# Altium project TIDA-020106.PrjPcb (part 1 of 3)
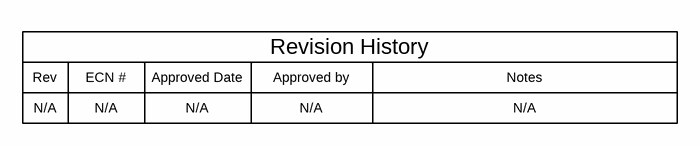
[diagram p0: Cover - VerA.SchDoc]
CopyrightYear: 2025; EVM_orderable: No; Orderable: NO; PCB_Layout: Hely Zhang; PCB_Rev: VerA; PRJ_Customer: Public Release; PRJ_Engineer: Hely Zhang; PRJ_Number: TIDA-020106; PRJ_Title: TIDA-020106; SCH_Rev: VerB; TechSupport: http://www.ti.com/support; TID: TIDA-020106
15 sheets, 408 parts. Net scope: hierarchical (ports join the sheet entries above them; power ports are global).
Board file: TIDA-020106.PcbDoc
Sheets:
  Cover - VerA.SchDoc
  Main.SchDoc
    U_DC_DC = DC_DC.SchDoc
    U_Hardware = Hardware.SchDoc
    DSP = DSP.SchDoc
      U_Clock_Reset = Clock_Reset.SchDoc
      U_ADC = ADC.SchDoc
      U_GPIO_Power = GPIO_Power.SchDoc
    CAN = CAN.SchDoc
    Sensor = Sensor.SchDoc
    PMIC = PMIC.SchDoc
    EPB = EPB.SchDoc
    BLDC = BLDC.SchDoc
    Ideal Diode = ID1_LM74930.SchDoc
  Cover - VerB.SchDoc

## Sheet Cover - VerA.SchDoc: Cover
size 431 x 279 mm; Date: Not shown in title block; ApprovedBy: Not shown in title block; CheckedBy: Not shown in title block; Author: Not shown in title block; CompanyName: Not shown in title block; Engineer: Not shown in title block; Organization: Not shown in title block; Address1: Not shown in title block; Address2: Not shown in title block; Address3: Not shown in title block; Address4: Not shown in title block; DocumentNumber: 1; Revision: Use project parameter SCH_Rev; SheetNumber: 1; SheetTotal: 15; PageSetup: Record=PageOptions¦CenterHorizontal=True¦CenterVertical=True¦PrintScale=1.00¦XCorrection=1.00¦YCorrection=1.00¦PrintKind=0¦BorderSize=5000000¦LeftOffset=0¦BottomOffset=0¦Orientation=2¦PaperLength=1000¦PaperWidth=1000¦Scale=100¦PaperSource=15¦PrintQuality=600¦MediaType=1¦DitherType=10¦PaperKind=Letter¦PrintScaleMode=1

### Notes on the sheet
- Rev
- N/A
- ECN #
- Approved Date
- Approved by
- Revision History
- Notes

## Sheet Main.SchDoc: Main
size 431 x 279 mm; Date: Not shown in title block; ApprovedBy: Not shown in title block; CheckedBy: Not shown in title block; Author: Not shown in title block; CompanyName: Not shown in title block; DrawnBy: Hely Zhang; Engineer: Not shown in title block; Organization: Not shown in title block; Address1: Not shown in title block; Address2: Not shown in title block; Address3: Not shown in title block; Address4: Not shown in title block; DocumentNumber: 2; Revision: Use project parameter SCH_Rev; SheetNumber: 2; SheetTotal: 15; PageSetup: Record=PageOptions¦CenterHorizontal=True¦CenterVertical=True¦PrintScale=1.00¦XCorrection=1.00¦YCorrection=1.00¦PrintKind=0¦BorderSize=5000000¦LeftOffset=0¦BottomOffset=0¦Orientation=2¦PaperLength=1000¦PaperWidth=1000¦Scale=100¦PaperSource=15¦PrintQuality=600¦MediaType=1¦DitherType=10¦PaperKind=Letter¦PrintScaleMode=1
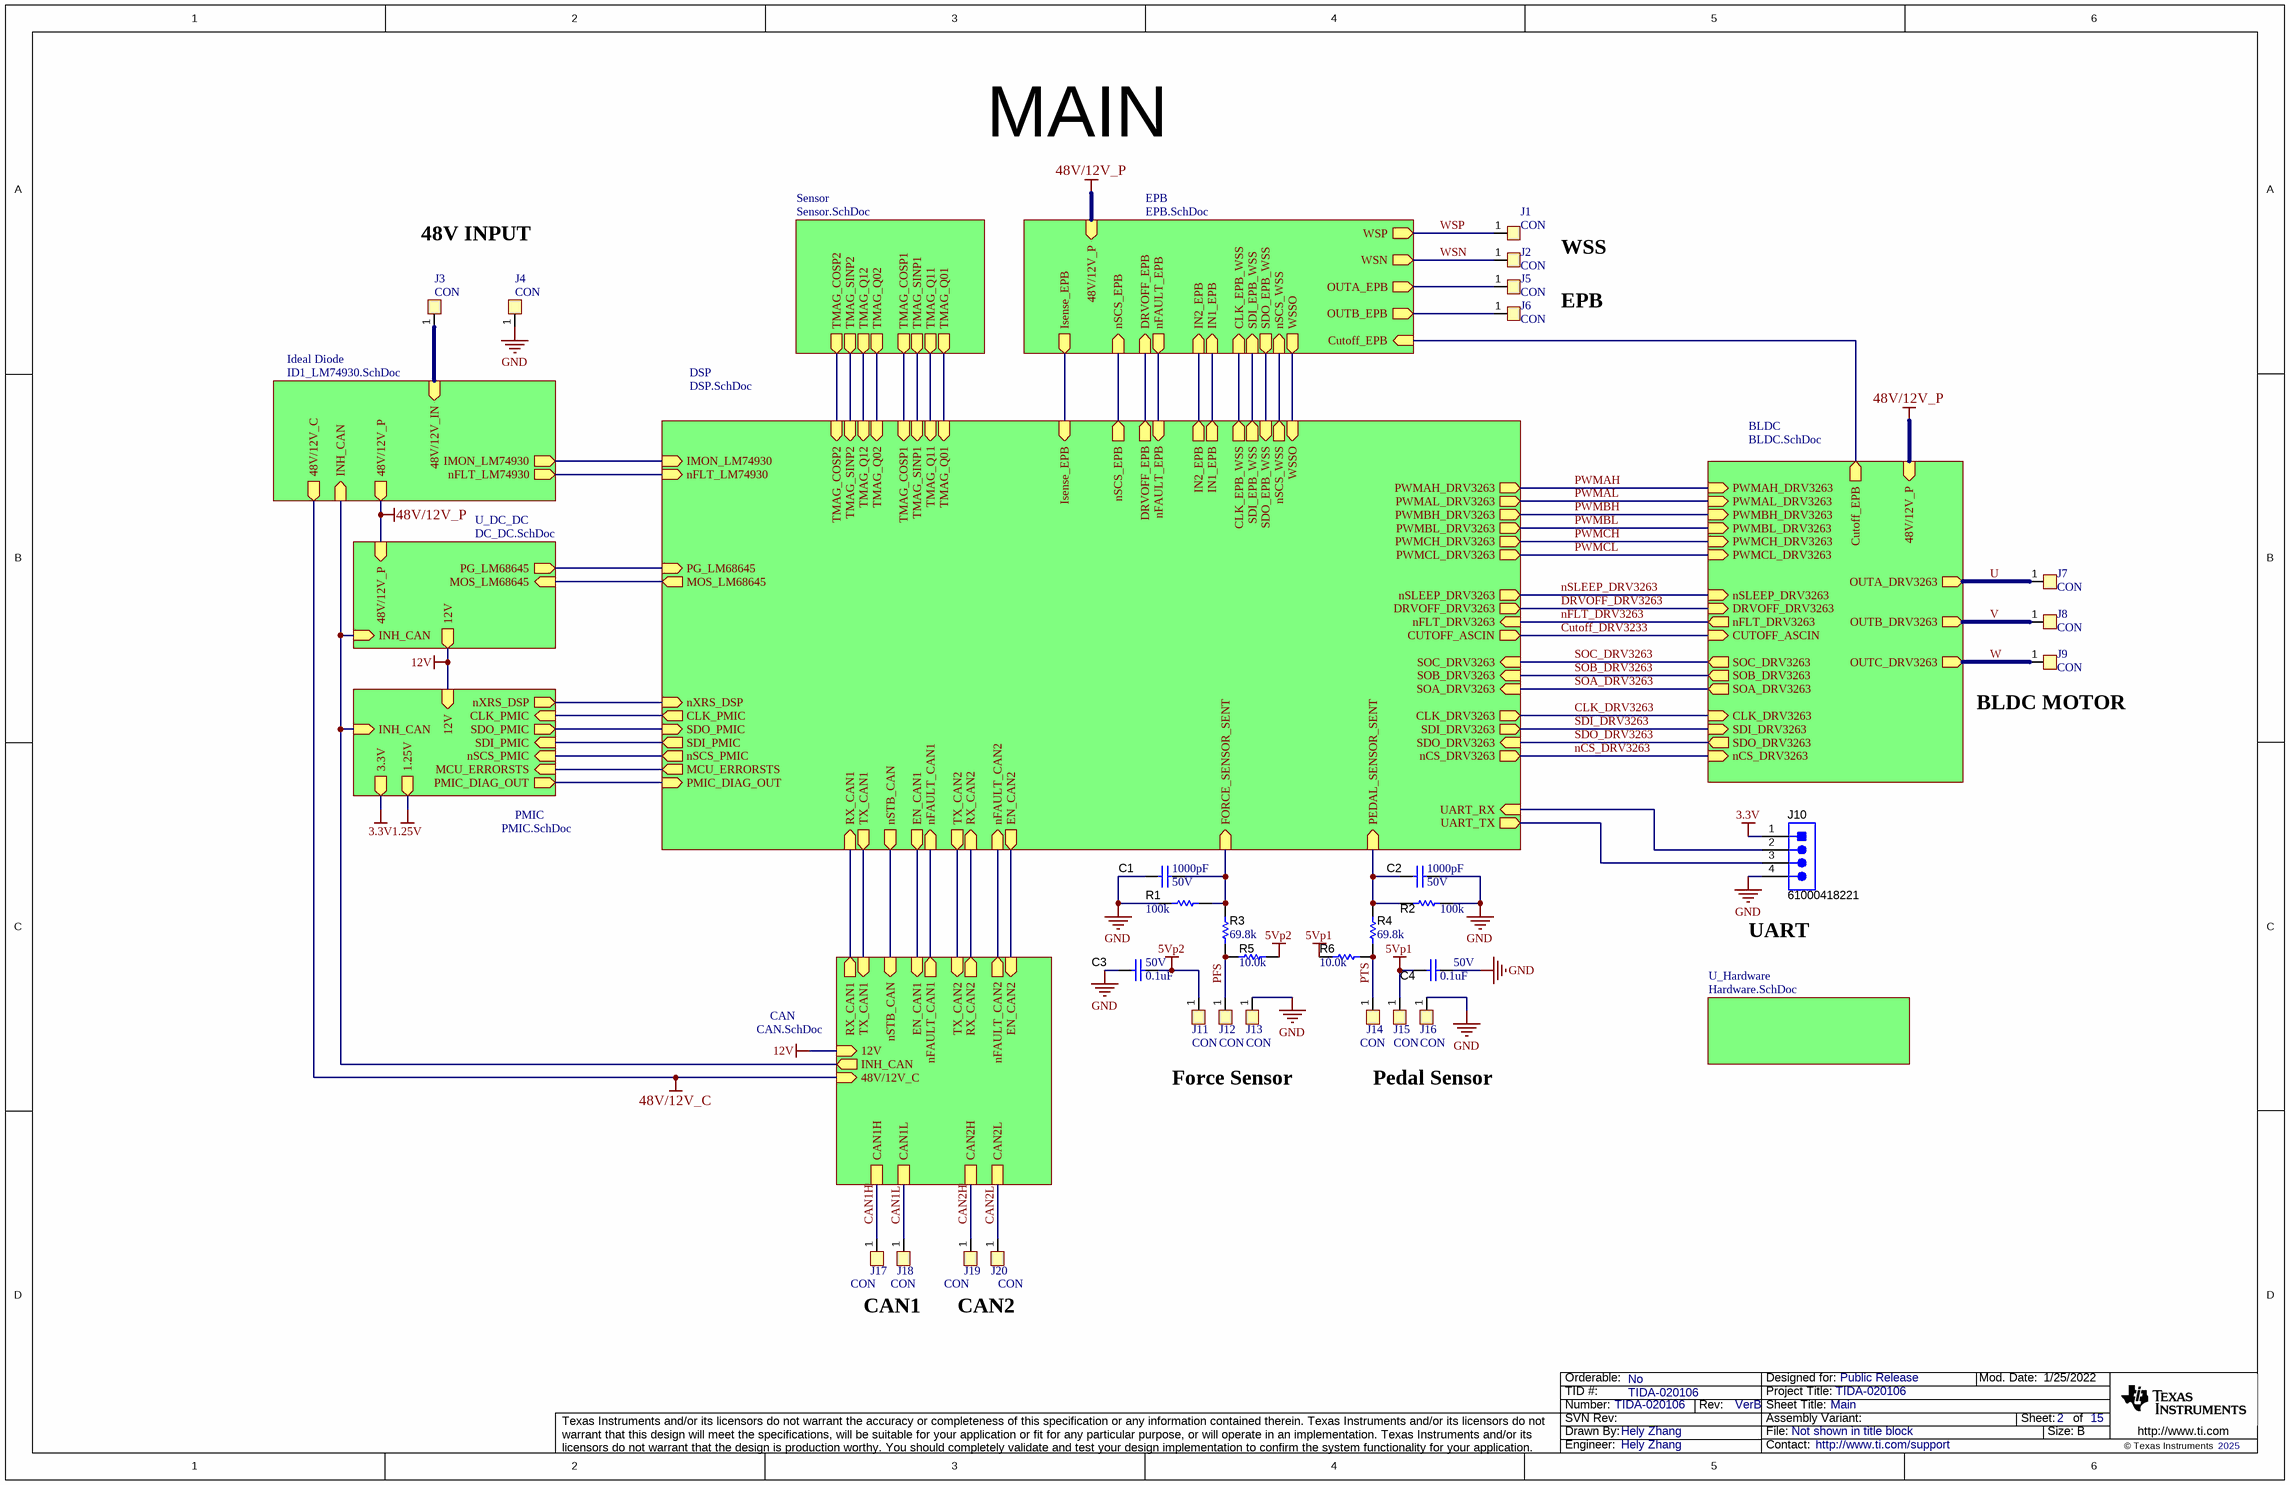
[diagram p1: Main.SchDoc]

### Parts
C1  ValueDisplayed: 1000pF  VDC_V: 50V  [0402]  (hidden comment: CGA2B2X8R1H102K050BA)
C2  ValueDisplayed: 1000pF  VDC_V: 50V  [0402]  (hidden comment: CGA2B2X8R1H102K050BA)
C3  VDC_V: 50V  ValueDisplayed: 0.1uF  [0402]  (hidden comment: GCM155R71H104KE02D)
C4  VDC_V: 50V  ValueDisplayed: 0.1uF  [0402]  (hidden comment: GCM155R71H104KE02D)
J1  CON  [Pin_1.7x1.1mm]
J2  CON  [Pin_1.7x1.1mm]
J3  CON  [Pin_3.3x1.3mm]
J4  CON  [Pin_3.3x1.3mm]
J5  CON  [Pin_1.9x0.9mm]
J6  CON  [Pin_1.9x0.9mm]
J7  CON  [Pin_3.3x1.4mm]
J8  CON  [Pin_3.3x1.4mm]
J9  CON  [Pin_3.3x1.4mm]
J10  61000418221  [Wurth_61000418221]
J11  CON  [Pin_1.7x1.1mm]
J12  CON  [Pin_1.7x1.1mm]
J13  CON  [Pin_1.7x1.1mm]
J14  CON  [Pin_1.7x1.1mm]
J15  CON  [Pin_3.3x1.3mm]
J16  CON  [Pin_1.7x1.1mm]
J17  CON  [Pin_1.7x1.1mm]
J18  CON  [Pin_1.7x1.1mm]
J19  CON  [Pin_1.7x1.1mm]
J20  CON  [Pin_1.7x1.1mm]
R1  ValueDisplayed: 100k  [0402]  (hidden comment: CRCW0402100KFKED)
R2  ValueDisplayed: 100k  [0402]  (hidden comment: CRCW0402100KFKED)
R3  ValueDisplayed: 69.8k  [0402]  (hidden comment: CRCW040269K8FKED)
R4  ValueDisplayed: 69.8k  [0402]  (hidden comment: CRCW040269K8FKED)
R5  ValueDisplayed: 10.0k  [0402]  (hidden comment: CRCW040210K0FKED)
R6  ValueDisplayed: 10.0k  [0402]  (hidden comment: CRCW040210K0FKED)

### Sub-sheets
BLDC = BLDC.SchDoc: nFLT_DRV3263 (out), PWMAH_DRV3263 (in), PWMAL_DRV3263 (in), PWMBH_DRV3263 (in), PWMBL_DRV3263 (in), PWMCH_DRV3263 (in), PWMCL_DRV3263 (in), SOC_DRV3263 (out), SOB_DRV3263 (out), SOA_DRV3263 (out), OUTA_DRV3263 (out), OUTB_DRV3263 (out), OUTC_DRV3263 (out), nCS_DRV3263 (in), CLK_DRV3263 (in), nSLEEP_DRV3263 (in), DRVOFF_DRV3263 (in), SDO_DRV3263 (out), SDI_DRV3263 (in), Cutoff_EPB (out), 48V/12V_P (in), CUTOFF_ASCIN (in)
CAN = CAN.SchDoc: TX_CAN1 (in), RX_CAN1 (out), nFAULT_CAN1 (out), EN_CAN1 (in), TX_CAN2 (in), RX_CAN2 (out), nFAULT_CAN2 (out), EN_CAN2 (in), 12V (in), 48V/12V_C (in), INH_CAN (out), CAN1H, CAN1L, CAN2L, CAN2H, nSTB_CAN (in)
DSP = DSP.SchDoc: CLK_PMIC (out), nSCS_PMIC (out), SOC_DRV3263 (in), SOB_DRV3263 (in), SOA_DRV3263 (in), PWMAH_DRV3263 (out), PWMAL_DRV3263 (out), PWMBH_DRV3263 (out), PWMBL_DRV3263 (out), PWMCH_DRV3263 (out), PWMCL_DRV3263 (out), nFLT_DRV3263 (in), TMAG_COSP2 (in), TMAG_SINP2 (in), TMAG_SINP1 (in), TMAG_COSP1 (in), FORCE_SENSOR_SENT (in), PEDAL_SENSOR_SENT (in), CLK_EPB_WSS (out), nFAULT_EPB (in), nSCS_WSS (out), nSCS_EPB (out), Isense_EPB (in), UART_TX (out), UART_RX (in), MCU_ERRORSTS (out), SDO_PMIC (in), SDI_PMIC (out), nXRS_DSP (in), PG_LM68645 (in), TX_CAN1 (out), RX_CAN1 (in), nFAULT_CAN1 (in), EN_CAN1 (out), TX_CAN2 (out), RX_CAN2 (in), nFAULT_CAN2 (in), EN_CAN2 (out), nSLEEP_DRV3263 (out), DRVOFF_DRV3263 (out), nCS_DRV3263 (out), CLK_DRV3263 (out), IN2_EPB (out), IN1_EPB (out), WSSO (in), SDI_DRV3263 (out), SDI_EPB_WSS (out), SDO_DRV3263 (in), SDO_EPB_WSS (in), nFLT_LM74930 (in), PMIC_DIAG_OUT (in), CUTOFF_ASCIN (out), TMAG_Q01 (in), TMAG_Q02 (in), TMAG_Q12 (in), TMAG_Q11 (in), IMON_LM74930 (in), DRVOFF_EPB (out), MOS_LM68645 (out), nSTB_CAN (out)
EPB = EPB.SchDoc: IN1_EPB (in), nFAULT_EPB (out), IN2_EPB (in), OUTA_EPB (out), OUTB_EPB (out), SDI_EPB_WSS (in), SDO_EPB_WSS (out), nSCS_EPB (in), Isense_EPB (out), WSSO (out), nSCS_WSS (in), CLK_EPB_WSS (in), 48V/12V_P (in), Cutoff_EPB (in), WSP (out), WSN (out), DRVOFF_EPB (in)
Ideal Diode = ID1_LM74930.SchDoc: nFLT_LM74930 (out), 48V/12V_P (out), 48V/12V_C (out), 48V/12V_IN (in), INH_CAN (in), IMON_LM74930 (out)
PMIC = PMIC.SchDoc: nSCS_PMIC (in), 12V (in), 3.3V (out), 1.25V (out), CLK_PMIC (in), SDO_PMIC (out), SDI_PMIC (in), nXRS_DSP (out), MCU_ERRORSTS (in), PMIC_DIAG_OUT (out), INH_CAN (in)
Sensor = Sensor.SchDoc: TMAG_COSP1 (out), TMAG_SINP1 (out), TMAG_COSP2 (out), TMAG_SINP2 (out), TMAG_Q01 (out), TMAG_Q02 (out), TMAG_Q12 (out), TMAG_Q11 (out)
U_DC_DC = DC_DC.SchDoc: PG_LM68645 (out), 12V (out), 48V/12V_P (in), INH_CAN (in), MOS_LM68645 (in)
U_Hardware = Hardware.SchDoc: no entries

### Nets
3.3V: J10.1 ; sheet PMIC/3.3V
5Vp1: C4.1 J15.1 R6.2
5Vp2: C3.2 J11.1 R5.1
12V: sheet U_DC_DC/12V, sheet CAN/12V, sheet PMIC/12V
48V/12V_C: sheet CAN/48V/12V_C, sheet Ideal Diode/48V/12V_C
48V/12V_IN: J3.1 ; sheet Ideal Diode/48V/12V_IN
48V/12V_P: sheet U_DC_DC/48V/12V_P, sheet EPB/48V/12V_P, sheet BLDC/48V/12V_P, sheet Ideal Diode/48V/12V_P
GND: C1.1 C2.2 C3.1 C4.2 J4.1 J10.4 J13.1 J16.1 R1.2 R2.1
BOOT1: J10.3 ; sheet DSP/UART_TX
CAN1H: J17.1 ; sheet CAN/CAN1H
CAN1L: J18.1 ; sheet CAN/CAN1L
CAN2H: J19.1 ; sheet CAN/CAN2H
CAN2L: J20.1 ; sheet CAN/CAN2L
CLK_DRV3263: sheet DSP/CLK_DRV3263, sheet BLDC/CLK_DRV3263
CLK_PMIC: sheet DSP/CLK_PMIC, sheet PMIC/CLK_PMIC
CLKEPB: sheet DSP/CLK_EPB_WSS, sheet EPB/CLK_EPB_WSS
Cutoff_DRV3233: sheet DSP/CUTOFF_ASCIN, sheet BLDC/CUTOFF_ASCIN  [project net CUTOFF_ASCIN]
Cutoff_EPB: sheet EPB/Cutoff_EPB, sheet BLDC/Cutoff_EPB
DRVOFF_DRV3263: sheet DSP/DRVOFF_DRV3263, sheet BLDC/DRVOFF_DRV3263
DRVOFF_EPB: sheet DSP/DRVOFF_EPB, sheet EPB/DRVOFF_EPB
EN_CAN1: sheet DSP/EN_CAN1, sheet CAN/EN_CAN1
EN_CAN2: sheet DSP/EN_CAN2, sheet CAN/EN_CAN2
FORCE_SENSOR_SENT: C1.2 R1.1 R3.2 ; sheet DSP/FORCE_SENSOR_SENT
IMON_LM74930: sheet DSP/IMON_LM74930, sheet Ideal Diode/IMON_LM74930
IN1_EPB: sheet DSP/IN1_EPB, sheet EPB/IN1_EPB
IN2_EPB: sheet DSP/IN2_EPB, sheet EPB/IN2_EPB
INH_CAN: sheet U_DC_DC/INH_CAN, sheet CAN/INH_CAN, sheet PMIC/INH_CAN, sheet Ideal Diode/INH_CAN
Isense_EPB: sheet DSP/Isense_EPB, sheet EPB/Isense_EPB
MCU_ERRORSTS: sheet DSP/MCU_ERRORSTS, sheet PMIC/MCU_ERRORSTS
MOS_LM68645: sheet U_DC_DC/MOS_LM68645, sheet DSP/MOS_LM68645
nCS_DRV3263: sheet DSP/nCS_DRV3263, sheet BLDC/nCS_DRV3263
nFAULT_CAN1: sheet DSP/nFAULT_CAN1, sheet CAN/nFAULT_CAN1
nFAULT_CAN2: sheet DSP/nFAULT_CAN2, sheet CAN/nFAULT_CAN2
nFAULT_EPB: sheet DSP/nFAULT_EPB, sheet EPB/nFAULT_EPB
nFLT_DRV3263: sheet DSP/nFLT_DRV3263, sheet BLDC/nFLT_DRV3263
nFLT_LM74930: sheet DSP/nFLT_LM74930, sheet Ideal Diode/nFLT_LM74930
nSCS_EPB: sheet DSP/nSCS_EPB, sheet EPB/nSCS_EPB
nSCS_PMIC: sheet DSP/nSCS_PMIC, sheet PMIC/nSCS_PMIC
nSCS_WSS: sheet DSP/nSCS_WSS, sheet EPB/nSCS_WSS
nSLEEP_DRV3263: sheet DSP/nSLEEP_DRV3263, sheet BLDC/nSLEEP_DRV3263
nSTB_CAN: sheet DSP/nSTB_CAN, sheet CAN/nSTB_CAN
nXRS_DSP: sheet DSP/nXRS_DSP, sheet PMIC/nXRS_DSP
OUTA_EPB: J5.1 ; sheet EPB/OUTA_EPB
OUTB_EPB: J6.1 ; sheet EPB/OUTB_EPB
PEDAL_SENSOR_SENT: C2.1 R2.2 R4.2 ; sheet DSP/PEDAL_SENSOR_SENT
PFS: J12.1 R3.1 R5.2
PG_LM68645: sheet U_DC_DC/PG_LM68645, sheet DSP/PG_LM68645
PMIC_DIAG_OUT: sheet DSP/PMIC_DIAG_OUT, sheet PMIC/PMIC_DIAG_OUT
PTS: J14.1 R4.1 R6.1
PWMAH: sheet DSP/PWMAH_DRV3263, sheet BLDC/PWMAH_DRV3263
PWMAL: sheet DSP/PWMAL_DRV3263, sheet BLDC/PWMAL_DRV3263
PWMBH: sheet DSP/PWMBH_DRV3263, sheet BLDC/PWMBH_DRV3263
PWMBL: sheet DSP/PWMBL_DRV3263, sheet BLDC/PWMBL_DRV3263
PWMCH: sheet DSP/PWMCH_DRV3263, sheet BLDC/PWMCH_DRV3263
PWMCL: sheet DSP/PWMCL_DRV3263, sheet BLDC/PWMCL_DRV3263
RX_CAN1: sheet DSP/RX_CAN1, sheet CAN/RX_CAN1
RX_CAN2: sheet DSP/RX_CAN2, sheet CAN/RX_CAN2
SDI_DRV3263: sheet DSP/SDI_DRV3263, sheet BLDC/SDI_DRV3263
SDI_PMIC: sheet DSP/SDI_PMIC, sheet PMIC/SDI_PMIC
SDIEPB: sheet DSP/SDI_EPB_WSS, sheet EPB/SDI_EPB_WSS
SDO_DRV3263: sheet DSP/SDO_DRV3263, sheet BLDC/SDO_DRV3263
SDO_PMIC: sheet DSP/SDO_PMIC, sheet PMIC/SDO_PMIC
SDOEPB: sheet DSP/SDO_EPB_WSS, sheet EPB/SDO_EPB_WSS
SOA_DRV3263: sheet DSP/SOA_DRV3263, sheet BLDC/SOA_DRV3263
SOB_DRV3263: sheet DSP/SOB_DRV3263, sheet BLDC/SOB_DRV3263
SOC_DRV3263: sheet DSP/SOC_DRV3263, sheet BLDC/SOC_DRV3263
TMAG_COSP1: sheet DSP/TMAG_COSP1, sheet Sensor/TMAG_COSP1
TMAG_COSP2: sheet DSP/TMAG_COSP2, sheet Sensor/TMAG_COSP2
TMAG_Q01: sheet DSP/TMAG_Q01, sheet Sensor/TMAG_Q01
TMAG_Q02: sheet DSP/TMAG_Q02, sheet Sensor/TMAG_Q02
TMAG_Q11: sheet DSP/TMAG_Q11, sheet Sensor/TMAG_Q11
TMAG_Q12: sheet DSP/TMAG_Q12, sheet Sensor/TMAG_Q12
TMAG_SINP1: sheet DSP/TMAG_SINP1, sheet Sensor/TMAG_SINP1
TMAG_SINP2: sheet DSP/TMAG_SINP2, sheet Sensor/TMAG_SINP2
TX_CAN1: sheet DSP/TX_CAN1, sheet CAN/TX_CAN1
TX_CAN2: sheet DSP/TX_CAN2, sheet CAN/TX_CAN2
U: J7.1 ; sheet BLDC/OUTA_DRV3263  [project net SHA]
UART_RX: J10.2 ; sheet DSP/UART_RX
V: J8.1 ; sheet BLDC/OUTB_DRV3263  [project net SHB]
W: J9.1 ; sheet BLDC/OUTC_DRV3263  [project net SHC]
WSN: J2.1 ; sheet EPB/WSN
WSP: J1.1 ; sheet EPB/WSP
WSSO: sheet DSP/WSSO, sheet EPB/WSSO

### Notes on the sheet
- MAIN
- 48V INPUT
- WSS
- EPB
- (near J9) BLDC MOTOR
- (near J10) UART
- Force Sensor
- Pedal Sensor
- CAN1
- CAN2

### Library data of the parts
C1 C2 = CMP-0860997-1: CAP, CERM, 1000 pF, 50 V,+/- 10%, X8R, AEC-Q200 Grade 0, 0402; Manufacturer: TDK; SizeArea_mm2: 0.5; U/M: EA; SizeX_mm: 1; Polarized: N; AEC Grade: 0; AEC Qualified: Y; TaMin_C: -55°C; Value: 1000pF; TaMax_C: 150°C; SizeZ_mm: 0.6; Cap_F: 1nF; SizeAreaWB_mm2: 3; AEC Category: Q200
C3 C4 = CMP-0006356-2: CAP, CERM, 0.1 uF, 50 V, +/- 10%, X7R, AEC-Q200 Grade 1, 0402; Manufacturer: MuRata; TaMin_C: -55°C; Polarized: N; SizeAreaWB_mm2: 3; Value1: Unknown; U/M: EA; Value: 0.1uF; TaMax_C: 125°C; SizeZ_mm: 0.6; SizeX_mm: 1; SizeY_mm: 0.5; AEC Qualified: Y; Cap_F: 100nF; AEC Category: Q200
J10 = CMP-0054788-1: Header, 2.54mm, 4x1, Gold, SMT; Manufacturer: Wurth Elektronik; CNHeader: TRUE; Shrouded: N; Gender: Male; Row_Count: 1; Pitch_mm: 2.54; CT: FALSE
R1 R2 = CMP-0025950-3: RES, 100 k, 1%, 0.063 W, AEC-Q200 Grade 0, 0402; Manufacturer: Vishay-Dale; Power_W: 63mW; TempCo: 100 ppm/C; Value: 100k; EIA_Code: E96; SizeX_mm: 1; SizeY_mm: 0.5; SizeZ_mm: 0.6; Value2: 0.063W; AEC Qualified: Y; VDC_V: 50V; AEC Category: Q200; AEC Grade: 0
R3 R4 = CMP-0026510-2: RES, 69.8 k, 1%, 0.063 W, AEC-Q200 Grade 0, 0402; Manufacturer: Vishay-Dale; Power_W: 63mW; TempCo: 100 ppm/C; Value_Code: 69k8; Value: 69.8k; EIA_Code: E96; SizeX_mm: 1; SizeY_mm: 0.5; SizeZ_mm: 0.6; Value2: 0.063W; AEC Qualified: Y; VDC_V: 50V; AEC Category: Q200; AEC Grade: 0
R5 R6 = CMP-0025958-3: RES, 10.0 k, 1%, 0.063 W, AEC-Q200 Grade 0, 0402; Manufacturer: Vishay-Dale; Power_W: 63mW; TempCo: 100 ppm/C; Value_Code: 10k0; Value: 10.0k; EIA_Code: E96; Res_ohm: 10k; SizeX_mm: 1; SizeY_mm: 0.5; SizeZ_mm: 0.6; Value2: 0.063W; AEC Qualified: Y; VDC_V: 50V; AEC Category: Q200; AEC Grade: 0

## Sheet DC_DC.SchDoc: DC/DC
size A4; Date: Not shown in title block; ApprovedBy: Not shown in title block; CheckedBy: Not shown in title block; Author: Not shown in title block; CompanyName: Not shown in title block; DrawnBy: Hely Zhang; Engineer: Not shown in title block; Organization: Not shown in title block; Address1: Not shown in title block; Address2: Not shown in title block; Address3: Not shown in title block; Address4: Not shown in title block; DocumentNumber: 1; Revision: Use project parameter SCH_Rev; SheetNumber: 4; SheetTotal: 15; PageSetup: Record=PageOptions¦CenterHorizontal=True¦CenterVertical=True¦PrintScale=1.00¦XCorrection=1.00¦YCorrection=1.00¦PrintKind=0¦BorderSize=5000000¦LeftOffset=0¦BottomOffset=0¦Orientation=2¦PaperLength=1000¦PaperWidth=1000¦Scale=100¦PaperSource=15¦PrintQuality=600¦MediaType=1¦DitherType=10¦PaperKind=Letter¦PrintScaleMode=1
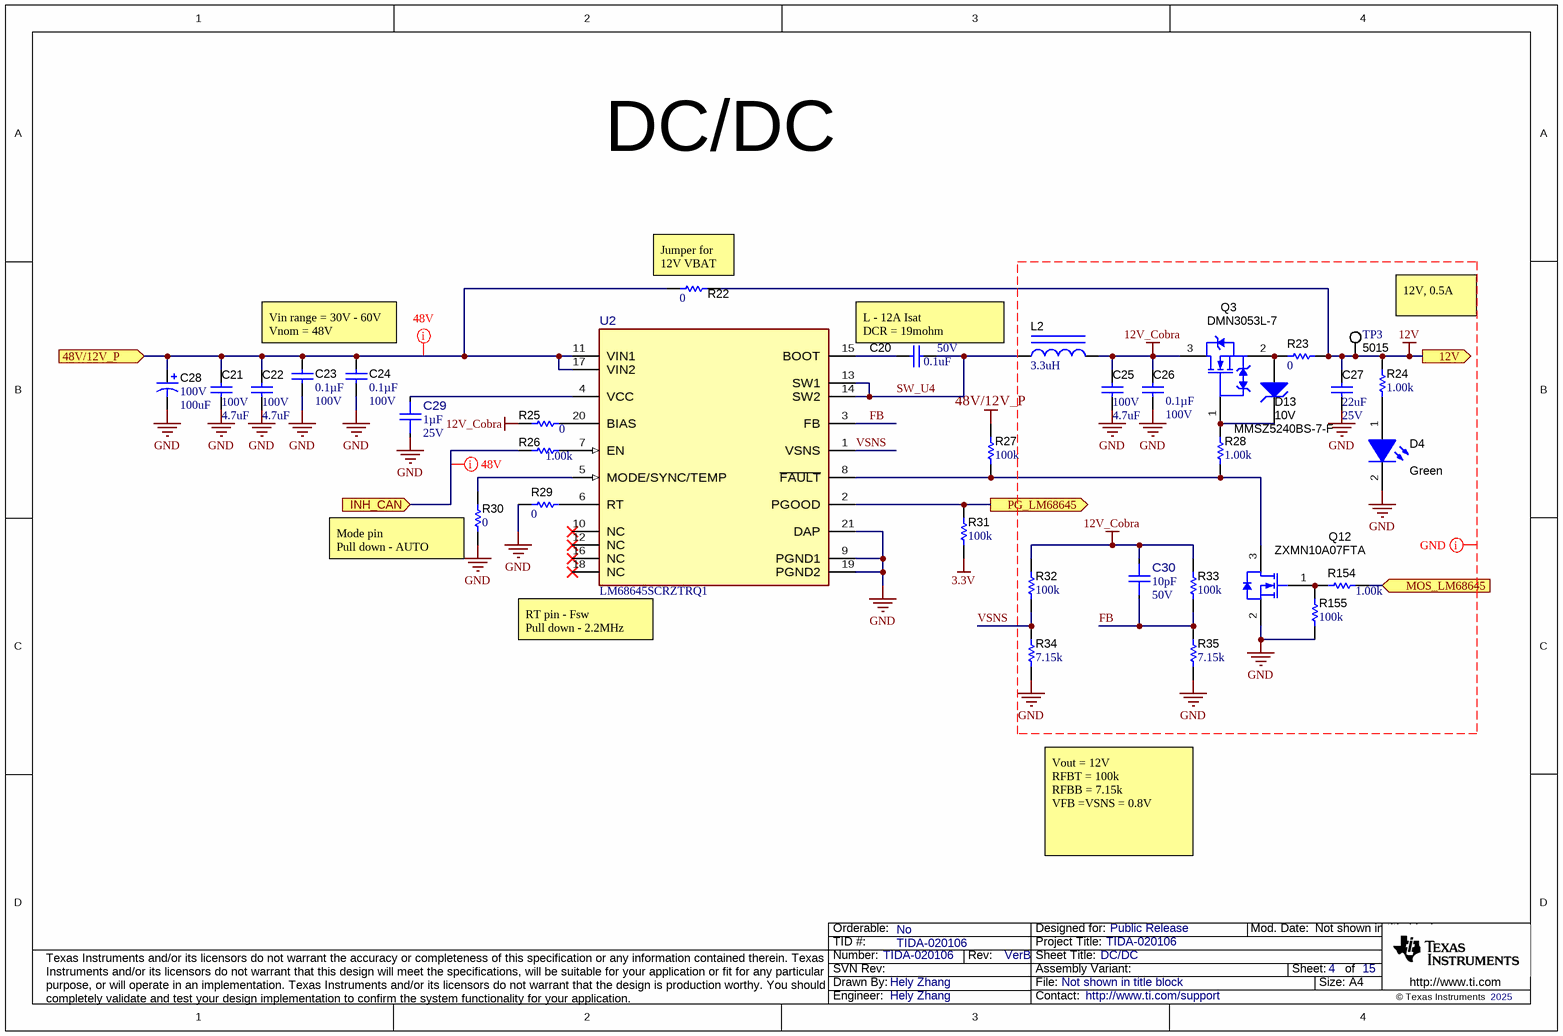
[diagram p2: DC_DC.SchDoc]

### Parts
C20  VDC_V: 50V  ValueDisplayed: 0.1uF  [0402]  (hidden comment: GCM155R71H104KE02D)
C21  VDC_V: 100V  ValueDisplayed: 4.7uF  [1210_220]  (hidden comment: GRM32DC72A475KE01L)
C22  VDC_V: 100V  ValueDisplayed: 4.7uF  [1210_220]  (hidden comment: GRM32DC72A475KE01L)
C23  ValueDisplayed: 0.1µF  VDC_V: 100V  [0603]  (hidden comment: GCJ188L8EL104KA07D)
C24  ValueDisplayed: 0.1µF  VDC_V: 100V  [0603]  (hidden comment: GCJ188L8EL104KA07D)
C25  VDC_V: 100V  ValueDisplayed: 4.7uF  [1210_220]  (hidden comment: GRM32DC72A475KE01L)
C26  ValueDisplayed: 0.1µF  VDC_V: 100V  [0603]  (hidden comment: GCJ188L8EL104KA07D)
C27  VDC_V: 25V  ValueDisplayed: 22uF  [0805_HV]  (hidden comment: GRM21BR61E226ME44L)
C28  VDC_V: 100V  ValueDisplayed: 100uF  [CAPSMT_62_LH0]  (hidden comment: EMVE101GTR101MLH0S)
C29  Cap_F: 1µF  VDC_V: 25V  [FP-AGC0603X7R250-105KXP_0603-MFG]  (hidden comment: AGC0603X7R250-105KXP)
C30  ValueDisplayed: 10pF  VDC_V: 50V  [FP-C0402C100K5RAC7867_0402-MFG]  (hidden comment: C0402C100K5RAC7867)
D4  value Green  [LTST-C191_Green]  (hidden comment: LTST-C191KGKT)
D13  MMSZ5240BS-7-F  value 10V  [SOD-323]
L2  ValueDisplayed: 3.3uH  [WE-LHMI_7050]  (hidden comment: 74437349033)
Q3  DMN3053L-7  [SOT-23]
Q12  ZXMN10A07FTA  [SOT-23]
R22  ValueDisplayed: 0  [0402]  (hidden comment: CRCW04020000Z0ED)
R23  ValueDisplayed: 0  [0402]  (hidden comment: CRCW04020000Z0ED)
R24  ValueDisplayed: 1.00k  [0402]  (hidden comment: CRCW04021K00FKED)
R25  ValueDisplayed: 0  [0402]  (hidden comment: CRCW04020000Z0ED)
R26  ValueDisplayed: 1.00k  [0402]  (hidden comment: CRCW04021K00FKED)
R27  ValueDisplayed: 100k  [0402]  (hidden comment: CRCW0402100KFKED)
R28  ValueDisplayed: 1.00k  [0402]  (hidden comment: CRCW04021K00FKED)
R29  ValueDisplayed: 0  [0402]  (hidden comment: CRCW04020000Z0ED)
R30  ValueDisplayed: 0  [0402]  (hidden comment: CRCW04020000Z0ED)
R31  ValueDisplayed: 100k  [0402]  (hidden comment: CRCW0402100KFKED)
R32  ValueDisplayed: 100k  [0402]  (hidden comment: CRCW0402100KFKED)
R33  ValueDisplayed: 100k  [0402]  (hidden comment: CRCW0402100KFKED)
R34  ValueDisplayed: 7.15k  [0402]  (hidden comment: CRCW04027K15FKED)
R35  ValueDisplayed: 7.15k  [0402]  (hidden comment: CRCW04027K15FKED)
R154  ValueDisplayed: 1.00k  [0402]  (hidden comment: CRCW04021K00FKED)
R155  ValueDisplayed: 100k  [0402]  (hidden comment: CRCW0402100KFKED)
TP3  5015  [Testpoint_Keystone_Miniature]
U2  LM68645SCRZTRQ1  [RZT0020A-MFG]

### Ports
12V (out), 48V/12V_P (in), INH_CAN (in), MOS_LM68645 (in), PG_LM68645 (out)

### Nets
3.3V: R31.1
12V: C27.1 R22.1 R23.1 R24.2 TP3.1 ; port 12V
12V_Cobra: C25.1 C26.2 C30.2 L2.2 Q3.3(D) R25.2 R32.1 R33.1
48V/12V_P: C21.1 C22.1 C23.2 C24.2 C28.1(+) R22.2 R27.1 U2.11(VIN1) U2.17(VIN2) ; port 48V/12V_P
GND: C21.2 C22.2 C23.1 C24.1 C25.2 C26.1 C27.2 C28.2(-) C29.1 D4.2(K) Q12.2(S) R29.1 R30.2 R34.1 R35.1 R155.2 U2.9(PGND1) U2.19(PGND2) U2.21(DAP)
FB: C30.1 R33.2 R35.2 U2.3(FB)
INH_CAN: R26.1 ; port INH_CAN
MOS_LM68645: R154.2 ; port MOS_LM68645
PG_LM68645: R31.2 U2.2(PGOOD) ; port PG_LM68645
SW_U4: C20.2 L2.1 U2.13(SW1) U2.14(SW2)
VSNS: R32.2 R34.2 U2.1(VSNS)
NetC20_1: C20.1 U2.15(BOOT)
NetC29_2: C29.2 U2.4(VCC)
NetD4_1: D4.1(A) R24.1
NetD13_1: D13.1(K) Q3.1(G) R28.1
NetD13_2: D13.2(A) Q3.2(S) R23.2
NetQ12_1: Q12.1(G) R154.1 R155.1
NetQ12_3: Q12.3(D) R27.2 R28.2 U2.8(~{FAULT})
NetR25_1: R25.1 U2.20(BIAS)
NetR26_2: R26.2 U2.7(EN)
NetR29_2: R29.2 U2.6(RT)
NetR30_1: R30.1 U2.5(MODE/SYNC/TEMP)

Not connected (* = marked no-connect by the designer): U2 10(NC)* 12(NC)* 16(NC)* 18(NC)*

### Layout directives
net class 48V: 48V/12V_P, INH_CAN
net class GND: 12V, 12V_Cobra, FB, GND

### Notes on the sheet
- DC/DC
- (near R22) Jumper for 12V VBAT
- 12V, 0.5A
- Vin range = 30V - 60V                        Vnom = 48V
- (near C20) L - 12A Isat
  DCR = 19mohm
- (near R30) Mode pin                           Pull down - AUTO
- (near U2) RT pin - Fsw                          Pull down - 2.2MHz
- Vout = 12V
  RFBT = 100k
  RFBB = 7.15k
  VFB =VSNS = 0.8V

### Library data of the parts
C20 = CMP-0006356-2: as C3 on sheet Main
C21 C22 C25 = CMP-0009182-2: CAP, CERM, 4.7 uF, 100 V, +/- 10%, X7S, 1210; Manufacturer: MuRata; TaMin_C: -55°C; Polarized: N; SizeAreaWB_mm2: 14.7; Value1: Unknown; U/M: EA; Value: 4.7uF; TaMax_C: 125°C; SizeZ_mm: 2.2; SizeX_mm: 3.2; SizeY_mm: 2.5; Cap_Case: 1210; SizeArea_mm2: 8; Cap_F: 4.7µF; AEC Category: Q200
C23 C24 C26 = CMP-0860999-1: CAP, CERM, 0.1 µF, 100 V,+/- 10%, X8L, AEC-Q200 Grade 0, 0603; Manufacturer: MuRata; Cap_F: 100nF; TaMax_C: 150°C; SizeAreaWB_mm2: 4.68; SizeArea_mm2: 1.28; Value: 0.1uF; SizeZ_mm: 1; AEC Qualified: Y; SizeX_mm: 1.6; AEC Grade: 0; SizeY_mm: 0.8; U/M: EA; TaMin_C: -55°C; Polarized: N; AEC Category: Q200
C27 = CMP-0008305-2: CAP, CERM, 22 uF, 25 V, +/- 20%, X5R, 0805; Manufacturer: MuRata; TaMin_C: -55°C; Polarized: N; SizeAreaWB_mm2: 6.75; Value1: Unknown; U/M: EA; Value: 22uF; TaMax_C: 85°C; SizeZ_mm: 1.45; SizeX_mm: 2; SizeY_mm: 1.25; Cap_Case: 0805; SizeArea_mm2: 2.5; Cap_F: 22µF; AEC Category: Q200
C28 = CMP-0011274-1: CAP, AL, 100 uF, 100 V, +/- 20%, SMD; Manufacturer: Chemi-Con; TaMin_C: -40°C; Polarized: Y; SizeAreaWB_mm2: 361; Value1: Unknown; U/M: EA; Value: 100uF; TaMax_C: 105°C; SizeZ_mm: 16.5; SizeX_mm: 17; Cap_Case: LH0; SizeArea_mm2: 289; CompType: Capacitor; Cap_F: 100µF; IRMS_A: 450mA; AEC Category: Q200
C29 = CMP-0123897-1: Auto Grade Capacitor, 0603, X7R, 25V, 1uF, ±10%; Manufacturer: Venkel; AEC Grade: Grade 1; AEC Qualified: Yes; SizeZ_mm: 0.95mm; TempCo: 15%; Value: 1µF
C30 = CMP-0122034-1: 10 pF ±10% 50V Ceramic Capacitor X7R 0402 (1005 Metric); Manufacturer: KEMET; AEC Qualified: No; SizeZ_mm: 0.55mm; TempCo: 15%; Value: 10pF
D4 = CMP-0078478-1: LED, Green, SMD; Manufacturer: Lite-On; Io_A: 30mA; Power_TotalModule: 75mW; Green_Lifecycle: Not Set; Vr_V: 5V; Tjmax_C: 85°C; Green_REACh: Incomplete; Value1: 0.075W; Angle: 130; Ir_A: 10µA; Vf_V: 2V; Type: AlInGaP
D13 = CMP-0005829-3: Diode, Zener, 10 V, 200 mW, SOD-323; Manufacturer: Diodes Inc.; SizeZ_mm: 1; Value1: 0.2W; SizeAreaWB_mm2: 8.695; SizeArea_mm2: 3.645; SizeY_mm: 1.35; SizeX_mm: 2.7; AEC Category: Q101; Power_W: 200mW; RJA_CperW: 350
L2 = CMP-0064107-1: Inductor, Shielded Drum Core, Powdered Iron, 3.3 uH, 6 A, 0.019 ohm, SMD; Manufacturer: Wurth Elektronik; Isat: 12A @ 20% inductance drop; Irms: 6A @ 40C rise; Green_Lifecycle: Active; SizeAreaWB_mm2: 73.96; DCR_ohm: 19m; Green_REACh: Passed; Value: 3.3uH; Imax_A: 6A; SizeZ_mm: 5; SizeX_mm: 6.6; SizeArea_mm2: 43.56; Ind_H: 3.3µH; AEC Category: Q200
Q3 = CMP-0000613-1: MOSFET, N-CH, 30 V, 4 A, AEC-Q101, SOT-23; Alternate Manufacturer: None; Manufacturer: Diodes Inc.; SizeZ_mm: 1.1; ChType: N; Value2: 7.3 nC; Value1: 0; VdsMax_V: 30V; SizeX_mm: 2.5; SizeY_mm: 3; Vgs_V: 12V; AEC Qualified: Y; Value: 30V; Rdson45_ohm: 50m; SizeArea_mm2: 7.5; AEC Category: Q101; IdsMax_A: 4A; SizeAreaWB_mm2: 14; U/M: EA; QgTyp_nC: 7.3
Q12 = CMP-0001041-2: MOSFET, N-CH, 100 V, 0.7 A, AEC-Q101, SOT-23; Alternate Manufacturer: None; Manufacturer: Diodes Inc.; RevisionId: 1; AccessRights: 2147483647; Folder: Unified Components\Transistors\MOSFET\N-Channel\VDS 100V - 200V\; ContentType: Component; SizeZ_mm: 1.1; ChType: N; Value2: 2.9 nC; VdsMax_V: 100V; SizeX_mm: 2.5; SizeY_mm: 3; Vgs_V: 20V; QgTyp_nC: 2.9; AEC Qualified: Y; Value: 100V; SizeArea_mm2: 7.5; AEC Category: Q101; IdsMax_A: 700mA; SizeAreaWB_mm2: 14; U/M: EA
R22 R23 R25 R29 R30 = CMP-0026822-3: RES, 0, 5%, 0.063 W, AEC-Q200 Grade 0, 0402; Manufacturer: Vishay-Dale; Power_W: 63mW; TempCo: 200 ppm/C; Value_Code: 0000; Value: 0; EIA_Code: E24; SizeX_mm: 1; SizeY_mm: 0.5; SizeZ_mm: 0.6; Value2: 0.063W; AEC Qualified: Y; VDC_V: 50V; AEC Category: Q200
R24 R26 R28 R154 = CMP-0026071-3: RES, 1.00 k, 1%, 0.063 W, AEC-Q200 Grade 0, 0402; Manufacturer: Vishay-Dale; Power_W: 63mW; TempCo: 100 ppm/C; Value_Code: 1k00; Value: 1.00k; EIA_Code: E96; Res_ohm: 1k; SizeX_mm: 1; SizeY_mm: 0.5; SizeZ_mm: 0.6; Value2: 0.063W; AEC Qualified: Y; VDC_V: 50V; AEC Category: Q200; AEC Grade: 0
R27 R31-R33 R155 = CMP-0025950-3: as R1 on sheet Main
R34 R35 = CMP-0026553-2: RES, 7.15 k, 1%, 0.063 W, AEC-Q200 Grade 0, 0402; Manufacturer: Vishay-Dale; Power_W: 63mW; TempCo: 100 ppm/C; Value_Code: 7k15; Value: 7.15k; EIA_Code: E96; SizeX_mm: 1; SizeY_mm: 0.5; SizeZ_mm: 0.6; Value2: 0.063W; AEC Qualified: Y; VDC_V: 50V; AEC Category: Q200; AEC Grade: 0
TP3 = CMP-0055152-1: Test Point, Miniature, SMT; Manufacturer: Keystone; CNHeader: FALSE; Green_Lifecycle: Active; Green_REACh: Passed; CT: TRUE
U2 = CMP-0096221-1: 3.5V to 65V Synchronous Step-Down Voltage Regulator; Manufacturer: Texas Instruments; Switching Topology: Buck; Number Of Outputs: 1; AEC Qualified: Yes; Standoff Height: 0mm; Output Type: AdjustableProgrammable; SizeZ_mm: 0.7mm

## Sheet Hardware.SchDoc
size 431 x 279 mm; Date: Not shown in title block; ApprovedBy: Not shown in title block; CheckedBy: Not shown in title block; Author: Not shown in title block; CompanyName: Not shown in title block; Engineer: Not shown in title block; Organization: Not shown in title block; Address1: Not shown in title block; Address2: Not shown in title block; Address3: Not shown in title block; Address4: Not shown in title block; DocumentNumber: 3; Revision: Use project parameter SCH_Rev; SheetNumber: 14; SheetTotal: 15; PageSetup: Record=PageOptions¦CenterHorizontal=True¦CenterVertical=True¦PrintScale=1.00¦XCorrection=1.00¦YCorrection=1.00¦PrintKind=0¦BorderSize=5000000¦LeftOffset=0¦BottomOffset=0¦Orientation=2¦PaperLength=1000¦PaperWidth=1000¦Scale=100¦PaperSource=15¦PrintQuality=600¦MediaType=1¦DitherType=10¦PaperKind=Letter¦PrintScaleMode=1
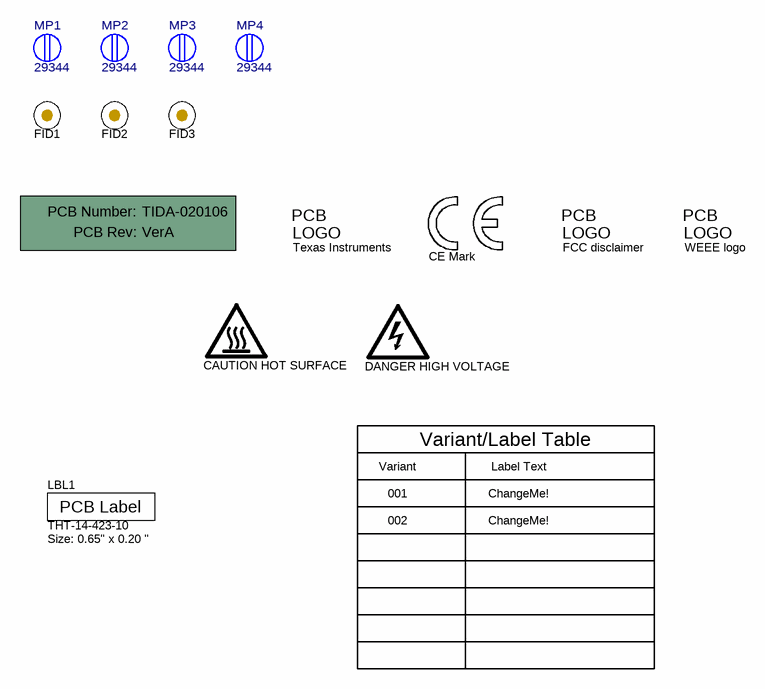
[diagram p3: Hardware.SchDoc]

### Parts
!PCB1  Printed Circuit Board  (value not drawn)  (mechanical)
FID1  Fiducial  [Fiducial10-20]  (value not drawn)
FID2  Fiducial  [Fiducial10-20]  (value not drawn)
FID3  Fiducial  [Fiducial10-20]  (value not drawn)
LBL1  THT-14-423-10  Note: Size: 0.65" x 0.20 "  [Label_650x200]
Logo1  CE Mark  [CE_Mark_5mm]  (no BOM)
Logo2  Texas Instruments  [TI_Stacked_Overlay_Small]  (no BOM)
Logo3  FCC disclaimer  [FCC_disclaimer]  (no BOM)
Logo4  WEEE logo  [WEEE_Minimum]  (no BOM)
LOGO5  CAUTION HOT SURFACE  [IEC_HotSurface_Small]  (no BOM)
LOGO6  DANGER HIGH VOLTAGE  [IEC_HighVoltage_Small]  (no BOM)
MP1  29344  [FP-29344_SCREW-MFG]
MP2  29344  [FP-29344_SCREW-MFG]
MP3  29344  [FP-29344_SCREW-MFG]
MP4  29344  [FP-29344_SCREW-MFG]

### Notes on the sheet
- Variant
- Variant/Label Table
- Label Text
- 001
- 002
- ChangeMe!

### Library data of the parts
!PCB1 = CMP-0003618-2: Manufacturer: Any; PartNumber: TIDA-020106
FID1-FID3 = CMP-0077181-1: Fiducial mark.  There is nothing to buy or mount.
LBL1 = CMP-0003625-1: Thermal Transfer Printable Labels, 0.650" W x 0.200" H - 10,000 per roll; Manufacturer: Brady; CompType: Label
Logo1 = CMP-0074844-1: SymbolCreator: a0412235
Logo2 = CMP-0074838-1: Texas Instrument Corporate Signature; SymbolCreator: a0412235; Lib Reference: TI_Logo; Library Reference: Logo
Logo3 = CMP-0074847-1: FCC_disclaimer; Library Reference: Logo
Logo4 = CMP-0074769-1
LOGO5 = CMP-0074837-1: IEC 61010-1 Hot Surface Warning; SymbolCreator: a0412235; Lib Reference: IEC_HotSurface
LOGO6 = CMP-0074835-1: IEC 61010-1 High Voltage Warning; SymbolCreator: a0412235; Lib Reference: IEC_HighVoltage
MP1-MP4 = CMP-0125643-1: M3 Pan Head Machine Screw Slotted Drive Nylon; Manufacturer: Keystone Electronics; AEC Qualified: No

## Sheet DSP.SchDoc: DSP
size A4; Date: Not shown in title block; ApprovedBy: Hely Zhang; CheckedBy: Not shown in title block; Author: Not shown in title block; CompanyName: Not shown in title block; DrawnBy: Hely Zhang; Engineer: Not shown in title block; Organization: Not shown in title block; Address1: Not shown in title block; Address2: Not shown in title block; Address3: Not shown in title block; Address4: Not shown in title block; DocumentNumber: 1; Revision: Use project parameter SCH_Rev; SheetNumber: 10; SheetTotal: 15; PageSetup: Record=PageOptions¦CenterHorizontal=True¦CenterVertical=True¦PrintScale=0.93¦XCorrection=1.00¦YCorrection=1.00¦PrintKind=0¦BorderSize=5000000¦LeftOffset=0¦BottomOffset=0¦Orientation=2¦PaperLength=1000¦PaperWidth=1000¦Scale=100¦PaperSource=15¦PrintQuality=600¦MediaType=1¦DitherType=10¦PaperKind=Letter¦PrintScaleMode=1
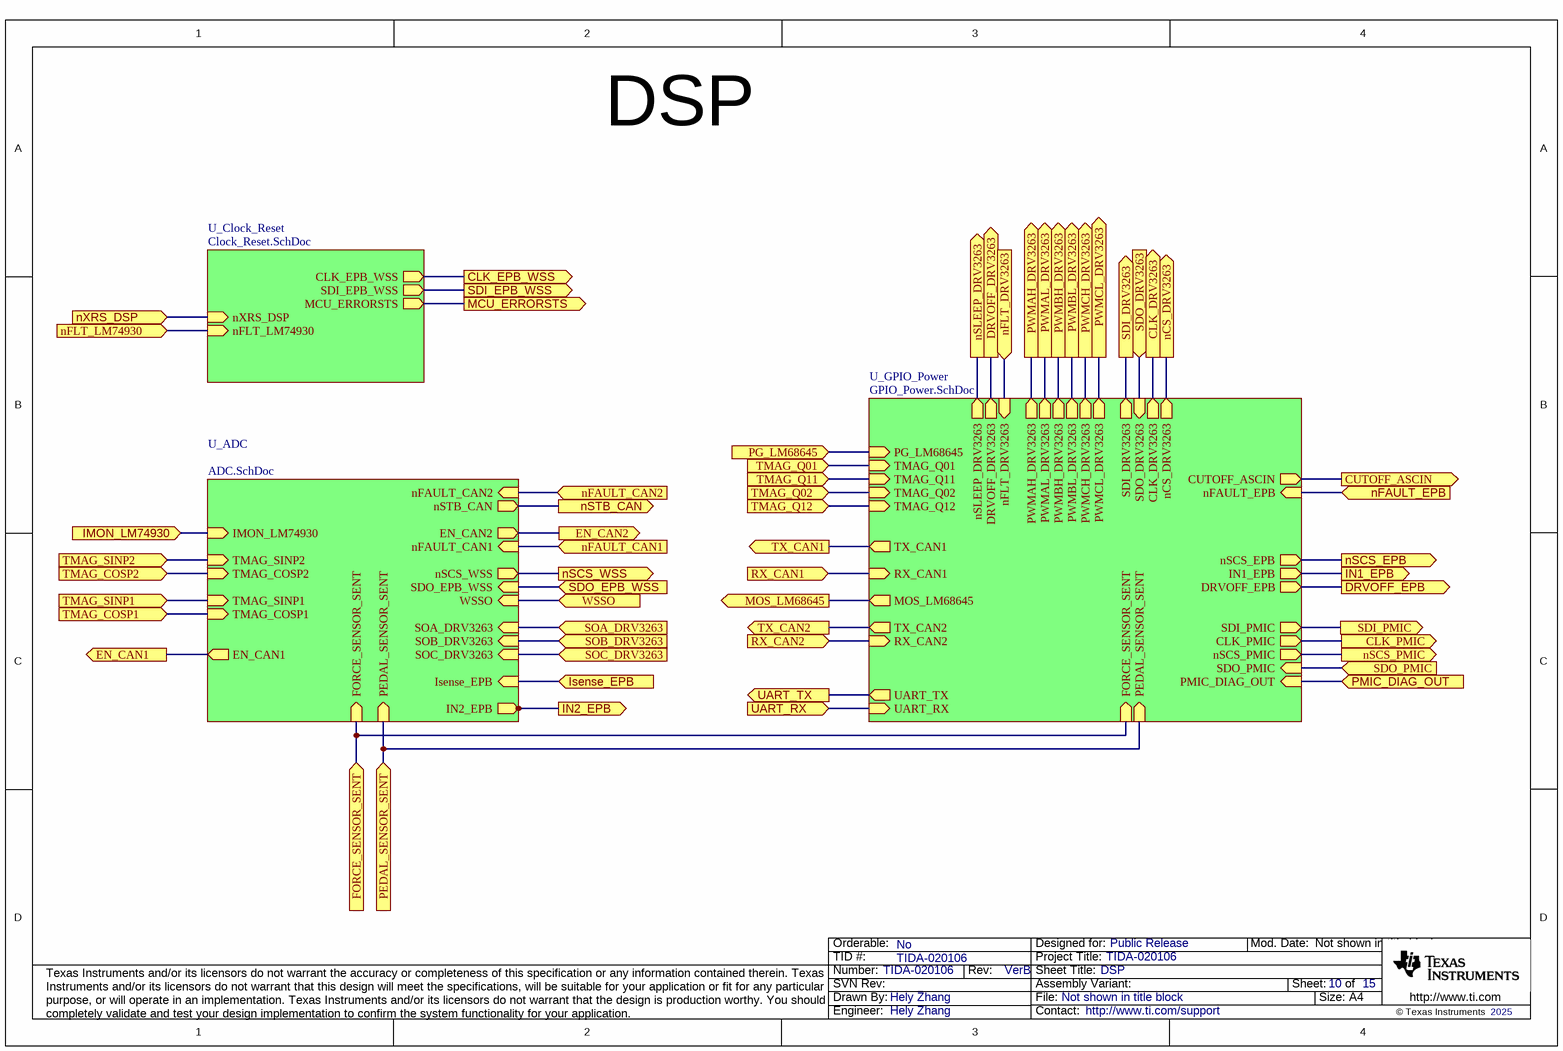
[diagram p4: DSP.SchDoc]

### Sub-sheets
U_ADC = ADC.SchDoc: TMAG_COSP2 (in), TMAG_SINP2 (in), TMAG_SINP1 (in), TMAG_COSP1 (in), SOC_DRV3263 (in), SOB_DRV3263 (in), SOA_DRV3263 (in), FORCE_SENSOR_SENT (in), PEDAL_SENSOR_SENT (in), Isense_EPB (in), SDO_EPB_WSS (in), nSCS_WSS (out), WSSO (in), nFAULT_CAN2 (in), EN_CAN2 (out), nFAULT_CAN1 (in), EN_CAN1 (out), IMON_LM74930 (in), IN2_EPB (out), nSTB_CAN (out)
U_Clock_Reset = Clock_Reset.SchDoc: MCU_ERRORSTS (out), nXRS_DSP (in), nFLT_LM74930 (in), CLK_EPB_WSS (out), SDI_EPB_WSS (out)
U_GPIO_Power = GPIO_Power.SchDoc: SDO_DRV3263 (in), SDI_DRV3263 (out), nSLEEP_DRV3263 (out), DRVOFF_DRV3263 (out), nCS_DRV3263 (out), CLK_DRV3263 (out), PWMAH_DRV3263 (out), PWMAL_DRV3263 (out), PWMBH_DRV3263 (out), PWMBL_DRV3263 (out), PWMCH_DRV3263 (out), PWMCL_DRV3263 (out), nFLT_DRV3263 (in), nFAULT_EPB (in), nSCS_EPB (out), UART_RX (in), UART_TX (out), IN1_EPB (out), FORCE_SENSOR_SENT (in), PEDAL_SENSOR_SENT (in), RX_CAN1 (in), RX_CAN2 (in), TX_CAN1 (out), TX_CAN2 (out), CUTOFF_ASCIN (out), SDI_PMIC (out), CLK_PMIC (out), nSCS_PMIC (out), SDO_PMIC (in), PMIC_DIAG_OUT (in), PG_LM68645 (in), TMAG_Q01 (in), TMAG_Q11 (in), TMAG_Q02 (in), TMAG_Q12 (in), DRVOFF_EPB (out), MOS_LM68645 (out)

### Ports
CLK_DRV3263 (out), CLK_EPB_WSS (out), CLK_PMIC (out), CUTOFF_ASCIN (out), DRVOFF_DRV3263 (out), DRVOFF_EPB (out), EN_CAN1 (out), EN_CAN2 (out), FORCE_SENSOR_SENT (in), IMON_LM74930 (in), IN1_EPB (out), IN2_EPB (out), Isense_EPB (in), MCU_ERRORSTS (out), MOS_LM68645 (out), nCS_DRV3263 (out), nFAULT_CAN1 (in), nFAULT_CAN2 (in), nFAULT_EPB (in), nFLT_DRV3263 (in), nFLT_LM74930 (in), nSCS_EPB (out), nSCS_PMIC (out), nSCS_WSS (out), nSLEEP_DRV3263 (out), nSTB_CAN (out), nXRS_DSP (in), PEDAL_SENSOR_SENT (in), PG_LM68645 (in), PMIC_DIAG_OUT (in), PWMAH_DRV3263 (out), PWMAL_DRV3263 (out), PWMBH_DRV3263 (out), PWMBL_DRV3263 (out), PWMCH_DRV3263 (out), PWMCL_DRV3263 (out), RX_CAN1 (in), RX_CAN2 (in), SDI_DRV3263 (out), SDI_EPB_WSS (out), SDI_PMIC (out), SDO_DRV3263 (in), SDO_EPB_WSS (in), SDO_PMIC (in), SOA_DRV3263 (in), SOB_DRV3263 (in), SOC_DRV3263 (in), TMAG_COSP1 (in), TMAG_COSP2 (in), TMAG_Q01 (in), TMAG_Q02 (in), TMAG_Q11 (in), TMAG_Q12 (in), TMAG_SINP1 (in), TMAG_SINP2 (in), TX_CAN1 (out), TX_CAN2 (out), UART_RX (in), UART_TX (out), WSSO (in)

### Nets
BOOT1: port UART_TX, sheet U_GPIO_Power/UART_TX
CLK_DRV3263: port CLK_DRV3263, sheet U_GPIO_Power/CLK_DRV3263
CLK_PMIC: port CLK_PMIC, sheet U_GPIO_Power/CLK_PMIC
CLKEPB: port CLK_EPB_WSS, sheet U_Clock_Reset/CLK_EPB_WSS
CUTOFF_ASCIN: port CUTOFF_ASCIN, sheet U_GPIO_Power/CUTOFF_ASCIN
DRVOFF_DRV3263: port DRVOFF_DRV3263, sheet U_GPIO_Power/DRVOFF_DRV3263
DRVOFF_EPB: port DRVOFF_EPB, sheet U_GPIO_Power/DRVOFF_EPB
EN_CAN1: port EN_CAN1, sheet U_ADC/EN_CAN1
EN_CAN2: port EN_CAN2, sheet U_ADC/EN_CAN2
FORCE_SENSOR_SENT: port FORCE_SENSOR_SENT, sheet U_ADC/FORCE_SENSOR_SENT, sheet U_GPIO_Power/FORCE_SENSOR_SENT
IMON_LM74930: port IMON_LM74930, sheet U_ADC/IMON_LM74930
IN1_EPB: port IN1_EPB, sheet U_GPIO_Power/IN1_EPB
IN2_EPB: port IN2_EPB, sheet U_ADC/IN2_EPB
Isense_EPB: port Isense_EPB, sheet U_ADC/Isense_EPB
MCU_ERRORSTS: port MCU_ERRORSTS, sheet U_Clock_Reset/MCU_ERRORSTS
MOS_LM68645: port MOS_LM68645, sheet U_GPIO_Power/MOS_LM68645
nCS_DRV3263: port nCS_DRV3263, sheet U_GPIO_Power/nCS_DRV3263
nFAULT_CAN1: port nFAULT_CAN1, sheet U_ADC/nFAULT_CAN1
nFAULT_CAN2: port nFAULT_CAN2, sheet U_ADC/nFAULT_CAN2
nFAULT_EPB: port nFAULT_EPB, sheet U_GPIO_Power/nFAULT_EPB
nFLT_DRV3263: port nFLT_DRV3263, sheet U_GPIO_Power/nFLT_DRV3263
nFLT_LM74930: port nFLT_LM74930, sheet U_Clock_Reset/nFLT_LM74930
nSCS_EPB: port nSCS_EPB, sheet U_GPIO_Power/nSCS_EPB
nSCS_PMIC: port nSCS_PMIC, sheet U_GPIO_Power/nSCS_PMIC
nSCS_WSS: port nSCS_WSS, sheet U_ADC/nSCS_WSS
nSLEEP_DRV3263: port nSLEEP_DRV3263, sheet U_GPIO_Power/nSLEEP_DRV3263
nSTB_CAN: port nSTB_CAN, sheet U_ADC/nSTB_CAN
nXRS_DSP: port nXRS_DSP, sheet U_Clock_Reset/nXRS_DSP
PEDAL_SENSOR_SENT: port PEDAL_SENSOR_SENT, sheet U_ADC/PEDAL_SENSOR_SENT, sheet U_GPIO_Power/PEDAL_SENSOR_SENT
PG_LM68645: port PG_LM68645, sheet U_GPIO_Power/PG_LM68645
PMIC_DIAG_OUT: port PMIC_DIAG_OUT, sheet U_GPIO_Power/PMIC_DIAG_OUT
PWMAH: port PWMAH_DRV3263, sheet U_GPIO_Power/PWMAH_DRV3263
PWMAL: port PWMAL_DRV3263, sheet U_GPIO_Power/PWMAL_DRV3263
PWMBH: port PWMBH_DRV3263, sheet U_GPIO_Power/PWMBH_DRV3263
PWMBL: port PWMBL_DRV3263, sheet U_GPIO_Power/PWMBL_DRV3263
PWMCH: port PWMCH_DRV3263, sheet U_GPIO_Power/PWMCH_DRV3263
PWMCL: port PWMCL_DRV3263, sheet U_GPIO_Power/PWMCL_DRV3263
RX_CAN1: port RX_CAN1, sheet U_GPIO_Power/RX_CAN1
RX_CAN2: port RX_CAN2, sheet U_GPIO_Power/RX_CAN2
SDI_DRV3263: port SDI_DRV3263, sheet U_GPIO_Power/SDI_DRV3263
SDI_PMIC: port SDI_PMIC, sheet U_GPIO_Power/SDI_PMIC
SDIEPB: port SDI_EPB_WSS, sheet U_Clock_Reset/SDI_EPB_WSS
SDO_DRV3263: port SDO_DRV3263, sheet U_GPIO_Power/SDO_DRV3263
SDO_PMIC: port SDO_PMIC, sheet U_GPIO_Power/SDO_PMIC
SDOEPB: port SDO_EPB_WSS, sheet U_ADC/SDO_EPB_WSS
SOA_DRV3263: port SOA_DRV3263, sheet U_ADC/SOA_DRV3263
SOB_DRV3263: port SOB_DRV3263, sheet U_ADC/SOB_DRV3263
SOC_DRV3263: port SOC_DRV3263, sheet U_ADC/SOC_DRV3263
TMAG_COSP1: port TMAG_COSP1, sheet U_ADC/TMAG_COSP1
TMAG_COSP2: port TMAG_COSP2, sheet U_ADC/TMAG_COSP2
TMAG_Q01: port TMAG_Q01, sheet U_GPIO_Power/TMAG_Q01
TMAG_Q02: port TMAG_Q02, sheet U_GPIO_Power/TMAG_Q02
TMAG_Q11: port TMAG_Q11, sheet U_GPIO_Power/TMAG_Q11
TMAG_Q12: port TMAG_Q12, sheet U_GPIO_Power/TMAG_Q12
TMAG_SINP1: port TMAG_SINP1, sheet U_ADC/TMAG_SINP1
TMAG_SINP2: port TMAG_SINP2, sheet U_ADC/TMAG_SINP2
TX_CAN1: port TX_CAN1, sheet U_GPIO_Power/TX_CAN1
TX_CAN2: port TX_CAN2, sheet U_GPIO_Power/TX_CAN2
UART_RX: port UART_RX, sheet U_GPIO_Power/UART_RX
WSSO: port WSSO, sheet U_ADC/WSSO

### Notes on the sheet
- DSP

## Sheet Clock_Reset.SchDoc: Clock&Reset
size A4; Date: Not shown in title block; ApprovedBy: Hely Zhang; CheckedBy: Not shown in title block; Author: Not shown in title block; CompanyName: Not shown in title block; DrawnBy: Hely Zhang; Engineer: Not shown in title block; Organization: Not shown in title block; Address1: Not shown in title block; Address2: Not shown in title block; Address3: Not shown in title block; Address4: Not shown in title block; DocumentNumber: 1; Revision: Use project parameter SCH_Rev; SheetNumber: 13; SheetTotal: 15; PageSetup: Record=PageOptions¦CenterHorizontal=True¦CenterVertical=True¦PrintScale=0.93¦XCorrection=1.00¦YCorrection=1.00¦PrintKind=0¦BorderSize=5000000¦LeftOffset=0¦BottomOffset=0¦Orientation=2¦PaperLength=1000¦PaperWidth=1000¦Scale=100¦PaperSource=15¦PrintQuality=600¦MediaType=1¦DitherType=10¦PaperKind=Letter¦PrintScaleMode=1
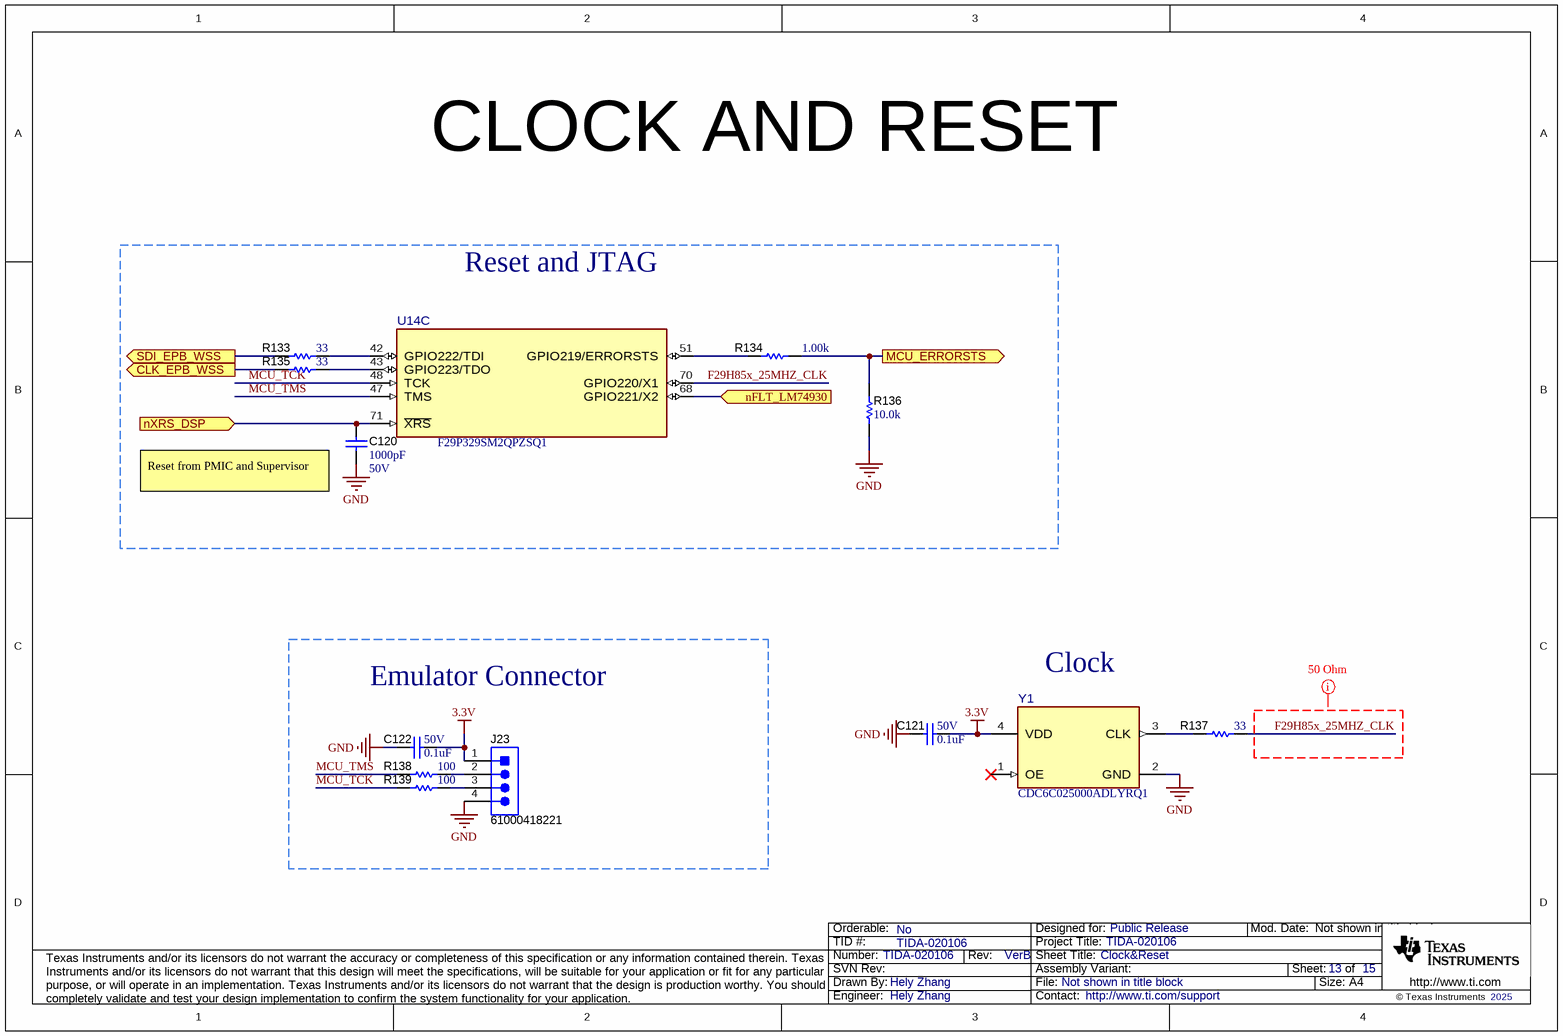
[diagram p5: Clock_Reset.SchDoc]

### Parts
C120  ValueDisplayed: 1000pF  VDC_V: 50V  [0402]  (hidden comment: CGA2B2X8R1H102K050BA)
C121  VDC_V: 50V  ValueDisplayed: 0.1uF  [0402]  (hidden comment: GCM155R71H104KE02D)
C122  VDC_V: 50V  ValueDisplayed: 0.1uF  [0402]  (hidden comment: GCM155R71H104KE02D)
J23  61000418221  [Wurth_61000418221]
R133  ValueDisplayed: 33  [0402]  (hidden comment: CRCW040233R0JNED)
R134  ValueDisplayed: 1.00k  [0402]  (hidden comment: CRCW04021K00FKED)
R135  ValueDisplayed: 33  [0402]  (hidden comment: CRCW040233R0JNED)
R136  ValueDisplayed: 10.0k  [0402]  (hidden comment: CRCW040210K0FKED)
R137  ValueDisplayed: 33  [0402]  (hidden comment: CRCW040233R0JNED)
R138  ValueDisplayed: 100  [0402]  (hidden comment: CRCW0402100RFKED)
R139  ValueDisplayed: 100  [0402]  (hidden comment: CRCW0402100RFKED)
U14  F29P329SM2QPZSQ1  [PZS0100A-MFG]  (part C of 4)
Y1  CDC6C025000ADLYRQ1  [DLY0004D-MFG]

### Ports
CLK_EPB_WSS (out), MCU_ERRORSTS (out), nFLT_LM74930 (in), nXRS_DSP (in), SDI_EPB_WSS (out)

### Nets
3.3V: C121.1 C122.1 J23.1 Y1.4(VDD)
GND: C120.2 C121.2 C122.2 J23.4 R136.2 Y1.2(GND)
CLKEPB: R135.1 ; port CLK_EPB_WSS
F29H85x_25MHZ_CLK: R137.2 U14.70(GPIO220/X1)
MCU_ERRORSTS: R134.1 R136.1 ; port MCU_ERRORSTS
MCU_TCK: R139.1 U14.48(TCK)
MCU_TMS: R138.1 U14.47(TMS)
nFLT_LM74930: U14.68(GPIO221/X2) ; port nFLT_LM74930
nXRS_DSP: C120.1 U14.71(~{XRS}) ; port nXRS_DSP
SDIEPB: R133.1 ; port SDI_EPB_WSS
NetJ23_2: J23.2 R138.2
NetJ23_3: J23.3 R139.2
NetR133_2: R133.2 U14.42(GPIO222/TDI)
NetR134_2: R134.2 U14.51(GPIO219/ERRORSTS)
NetR135_2: R135.2 U14.43(GPIO223/TDO)
NetR137_1: R137.1 Y1.3(CLK)

Not connected (* = marked no-connect by the designer): Y1 1(OE)*

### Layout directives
mark named 50 Ohm: (no net found under the mark)

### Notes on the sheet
- CLOCK AND RESET
- Reset and JTAG
- (near C120) Reset from PMIC and Supervisor
- Emulator Connector
- Clock

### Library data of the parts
C120 = CMP-0860997-1: as C1 on sheet Main
C121 C122 = CMP-0006356-2: as C3 on sheet Main
J23 = CMP-0054788-1: as J10 on sheet Main
R133 R135 R137 = CMP-0026908-3: RES, 33, 5%, 0.063 W, AEC-Q200 Grade 0, 0402; Manufacturer: Vishay-Dale; Power_W: 63mW; TempCo: 200 ppm/C; Value_Code: 33R0; Value: 33; EIA_Code: E24; SizeX_mm: 1; SizeY_mm: 0.5; SizeZ_mm: 0.6; Value2: 0.063W; AEC Qualified: Y; VDC_V: 50V; AEC Category: Q200; AEC Grade: 0
R134 = CMP-0026071-3: as R24 on sheet DC_DC
R136 = CMP-0025958-3: as R5 on sheet Main
R138 R139 = CMP-0025951-3: RES, 100, 1%, 0.063 W, AEC-Q200 Grade 0, 0402; Manufacturer: Vishay-Dale; Power_W: 63mW; TempCo: 100 ppm/C; Value_Code: 100R; Value: 100; EIA_Code: E96; SizeX_mm: 1; SizeY_mm: 0.5; SizeZ_mm: 0.6; Value2: 0.063W; AEC Qualified: Y; VDC_V: 50V; AEC Category: Q200; AEC Grade: 0
U14 = CMP-0128482-1: Real-Time Microcontrollers; Manufacturer: Texas Instruments; SizeZ_mm: 1.2mm; AEC Qualified: Yes; AEC Grade: Grade 1; Core Architecture: C29x; Data Bus Width: 64bits; Frequency_Fixed: 200MHz; Interface: I2C,SPI,UART,CAN,LIN; Max Supply Voltage: 3.63V; Memory Size: 2MBytes; Memory Type: FLASH; Min Supply Voltage: 1.19V; Number Of A/D Converters: 1; Number Of Adc Channels: 24; Number Of Cores: 2; Number Of I/Os: 46; Number Of Spi Channels: 5; Ram Size: 260KBytes; Standoff Height: 0.05mm; TaMax_C: +125°C; TaMin_C: -40°C; TJmax_C: +150°C
Y1 = CMP-0128115-1: Automotive, low-power, low-ppm, bulk-acoustic-wave (BAW), fixed-frequency LVCMOS oscillator 4-VSON -40 to 125; Manufacturer: Texas Instruments; SizeZ_mm: 1mm; AEC Qualified: Yes; AEC Grade: Grade 1; Frequency Stability: 25ppm; Frequency_Fixed: 25MHz; Load Capacitance: 30pF; Max Supply Voltage: 3.63V; Min Supply Voltage: 1.62V; Standoff Height: 0mm; TaMax_C: +125°C; TaMin_C: -40°C; TJmax_C: +130°C

## Sheet ADC.SchDoc: ADC
size A4; Date: Not shown in title block; ApprovedBy: Hely Zhang; CheckedBy: Not shown in title block; Author: Not shown in title block; CompanyName: Not shown in title block; DrawnBy: Hely Zhang; Engineer: Not shown in title block; Organization: Not shown in title block; Address1: Not shown in title block; Address2: Not shown in title block; Address3: Not shown in title block; Address4: Not shown in title block; DocumentNumber: 1; Revision: Use project parameter SCH_Rev; SheetNumber: 12; SheetTotal: 15; PageSetup: Record=PageOptions¦CenterHorizontal=True¦CenterVertical=True¦PrintScale=0.93¦XCorrection=1.00¦YCorrection=1.00¦PrintKind=0¦BorderSize=5000000¦LeftOffset=0¦BottomOffset=0¦Orientation=2¦PaperLength=1000¦PaperWidth=1000¦Scale=100¦PaperSource=15¦PrintQuality=600¦MediaType=1¦DitherType=10¦PaperKind=Letter¦PrintScaleMode=1
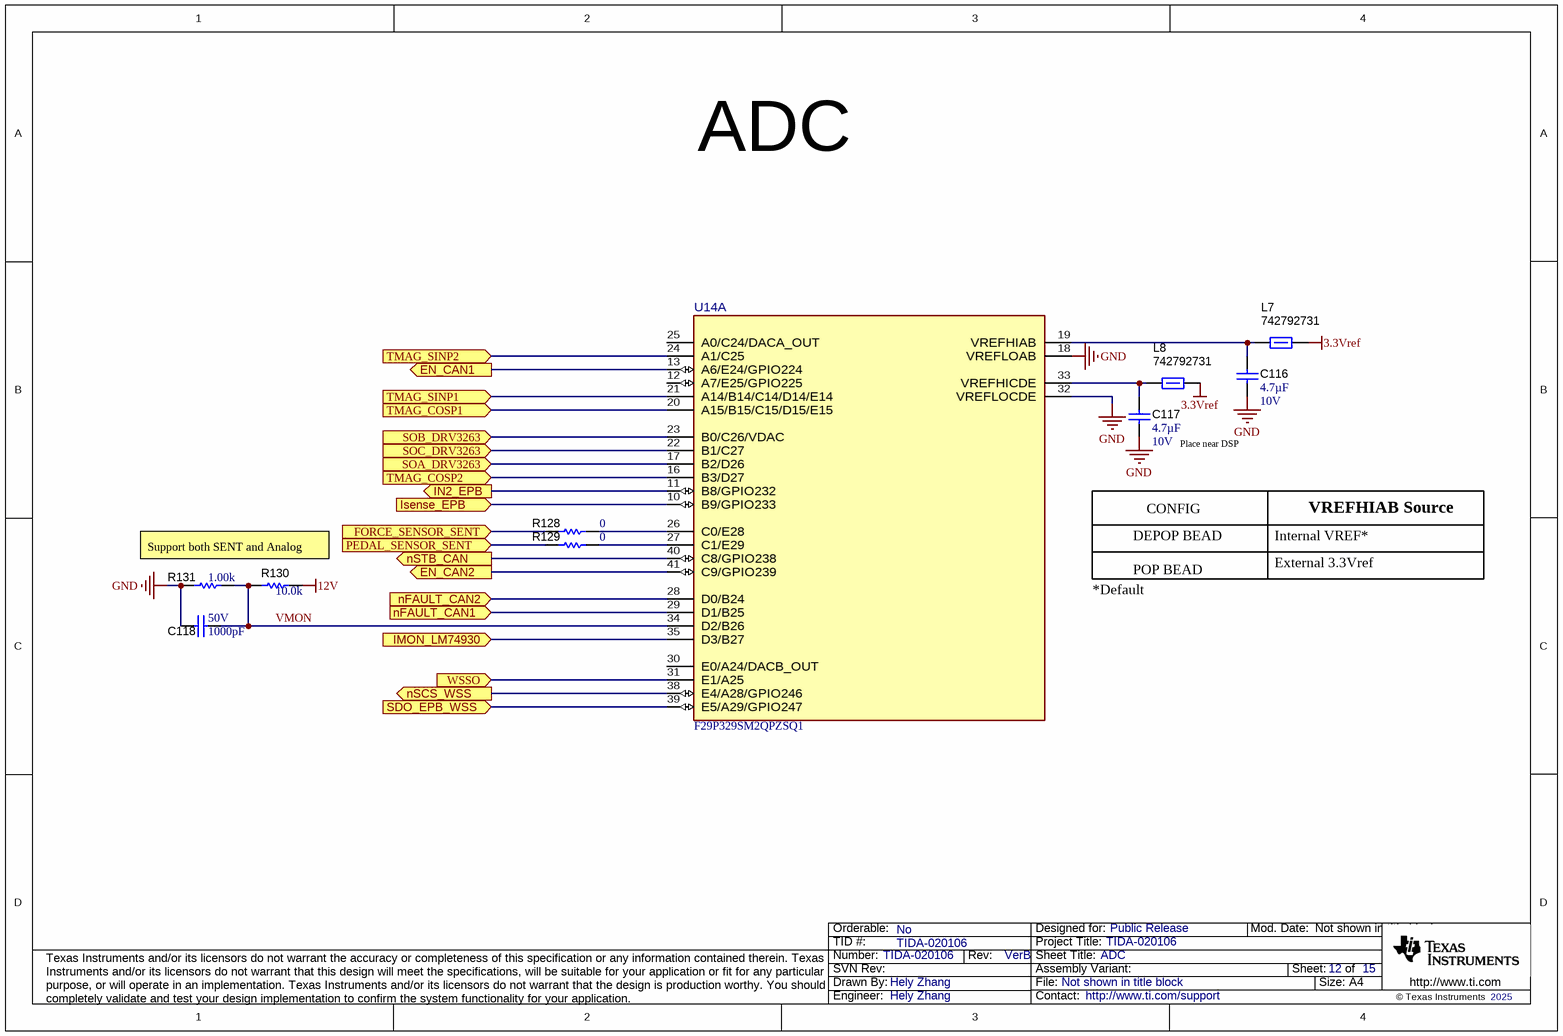
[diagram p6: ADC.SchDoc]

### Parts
C116  Cap_F: 4.7µF  VDC_V: 10V  [0603]  (hidden comment: GRM188Z71A475ME15D)
C117  Cap_F: 4.7µF  VDC_V: 10V  [0603]  (hidden comment: GRM188Z71A475ME15D)
C118  ValueDisplayed: 1000pF  VDC_V: 50V  [0402]  (hidden comment: CGA2B2X8R1H102K050BA)
L7  742792731  [0402]
L8  742792731  [0402]
R128  ValueDisplayed: 0  [0402]  (hidden comment: CRCW04020000Z0ED)
R129  ValueDisplayed: 0  [0402]  (hidden comment: CRCW04020000Z0ED)
R130  ValueDisplayed: 10.0k  [0402]  (hidden comment: CRCW040210K0FKED)
R131  ValueDisplayed: 1.00k  [0402]  (hidden comment: CRCW04021K00FKED)
U14  F29P329SM2QPZSQ1  [PZS0100A-MFG]  (part A of 4)

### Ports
EN_CAN1 (out), EN_CAN2 (out), FORCE_SENSOR_SENT (in), IMON_LM74930 (in), IN2_EPB (out), Isense_EPB (in), nFAULT_CAN1 (in), nFAULT_CAN2 (in), nSCS_WSS (out), nSTB_CAN (out), PEDAL_SENSOR_SENT (in), SDO_EPB_WSS (in), SOA_DRV3263 (in), SOB_DRV3263 (in), SOC_DRV3263 (in), TMAG_COSP1 (in), TMAG_COSP2 (in), TMAG_SINP1 (in), TMAG_SINP2 (in), WSSO (in)

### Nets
3.3Vref: L7.1 L8.1
12V: R130.1
GND: C116.2 C117.2 C118.1 R131.1 U14.18(VREFLOAB) U14.32(VREFLOCDE)
EN_CAN1: U14.13(A6/E24/GPIO224) ; port EN_CAN1
EN_CAN2: U14.41(C9/GPIO239) ; port EN_CAN2
FORCE_SENSOR_SENT: R128.2 ; port FORCE_SENSOR_SENT
IMON_LM74930: U14.35(D3/B27) ; port IMON_LM74930
IN2_EPB: U14.11(B8/GPIO232) ; port IN2_EPB
Isense_EPB: U14.10(B9/GPIO233) ; port Isense_EPB
nFAULT_CAN1: U14.29(D1/B25) ; port nFAULT_CAN1
nFAULT_CAN2: U14.28(D0/B24) ; port nFAULT_CAN2
nSCS_WSS: U14.38(E4/A28/GPIO246) ; port nSCS_WSS
nSTB_CAN: U14.40(C8/GPIO238) ; port nSTB_CAN
PEDAL_SENSOR_SENT: R129.2 ; port PEDAL_SENSOR_SENT
SDOEPB: U14.39(E5/A29/GPIO247) ; port SDO_EPB_WSS
SOA_DRV3263: U14.17(B2/D26) ; port SOA_DRV3263
SOB_DRV3263: U14.23(B0/C26/VDAC) ; port SOB_DRV3263
SOC_DRV3263: U14.22(B1/C27) ; port SOC_DRV3263
TMAG_COSP1: U14.20(A15/B15/C15/D15/E15) ; port TMAG_COSP1
TMAG_COSP2: U14.16(B3/D27) ; port TMAG_COSP2
TMAG_SINP1: U14.21(A14/B14/C14/D14/E14) ; port TMAG_SINP1
TMAG_SINP2: U14.24(A1/C25) ; port TMAG_SINP2
VMON: C118.2 R130.2 R131.2 U14.34(D2/B26)
WSSO: U14.31(E1/A25) ; port WSSO
NetC116_1: C116.1 L7.2 U14.19(VREFHIAB)
NetC117_1: C117.1 L8.2 U14.33(VREFHICDE)
NetR128_1: R128.1 U14.26(C0/E28)
NetR129_1: R129.1 U14.27(C1/E29)

Not connected (* = marked no-connect by the designer): U14 12(A7/E25/GPIO225) 25(A0/C24/DACA_OUT) 30(E0/A24/DACB_OUT)

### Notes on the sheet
- ADC
- Place near DSP
- CONFIG
- VREFHIAB Source
- Support both SENT and Analog
- DEPOP BEAD
- POP BEAD
- Internal VREF*
- External 3.3Vref
- (near U14) *Default

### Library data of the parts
C116 C117 = CMP-0007498-2: CAP, CERM, 4.7 uF, 10 V, +/- 20%, X7R, 0603; Manufacturer: MuRata; TaMin_C: -55°C; Polarized: N; SizeAreaWB_mm2: 4.68; Value1: Unknown; U/M: EA; Value: 4.7uF; TaMax_C: 125°C; SizeZ_mm: 1; SizeX_mm: 1.6; SizeY_mm: 0.8; SizeArea_mm2: 1.28; AEC Category: Q200
C118 = CMP-0860997-1: as C1 on sheet Main
L7 L8 = CMP-0003235-1: Ferrite Bead, 100 ohm @ 100 MHz, 1.2 A, 0402; Manufacturer: Wurth Elektronik; Ztyp@1GHz_Ohm: 149.261; ZTyp@100MHz_Ohm: 100; SizeAreaWB_mm2: 3; DCR_ohm: 90m; Value1: 0.09 ohm; Value: 100 ohm; Imax_A: 1.2A; SizeZ_mm: 0.6; SizeX_mm: 1; SizeY_mm: 0.5
R128 R129 = CMP-0026822-3: as R22 on sheet DC_DC
R130 = CMP-0025958-3: as R5 on sheet Main
R131 = CMP-0026071-3: as R24 on sheet DC_DC
U14 = CMP-0128482-1: as U14 on sheet Clock_Reset

## Sheet GPIO_Power.SchDoc: GPIO and Power
size 431 x 279 mm; Date: Not shown in title block; ApprovedBy: Not shown in title block; CheckedBy: Not shown in title block; Author: Not shown in title block; CompanyName: Not shown in title block; DrawnBy: Gustavo Martinez; Engineer: Not shown in title block; Organization: Not shown in title block; Address1: Not shown in title block; Address2: Not shown in title block; Address3: Not shown in title block; Address4: Not shown in title block; DocumentNumber: 8; Revision: Use project parameter SCH_Rev; SheetNumber: 11; SheetTotal: 15; PageSetup: Record=PageOptions¦CenterHorizontal=True¦CenterVertical=True¦PrintScale=1.00¦XCorrection=1.00¦YCorrection=1.00¦PrintKind=0¦BorderSize=5000000¦LeftOffset=0¦BottomOffset=0¦Orientation=2¦PaperLength=1000¦PaperWidth=1000¦Scale=100¦PaperSource=15¦PrintQuality=600¦MediaType=1¦DitherType=10¦PaperKind=Letter¦PrintScaleMode=1
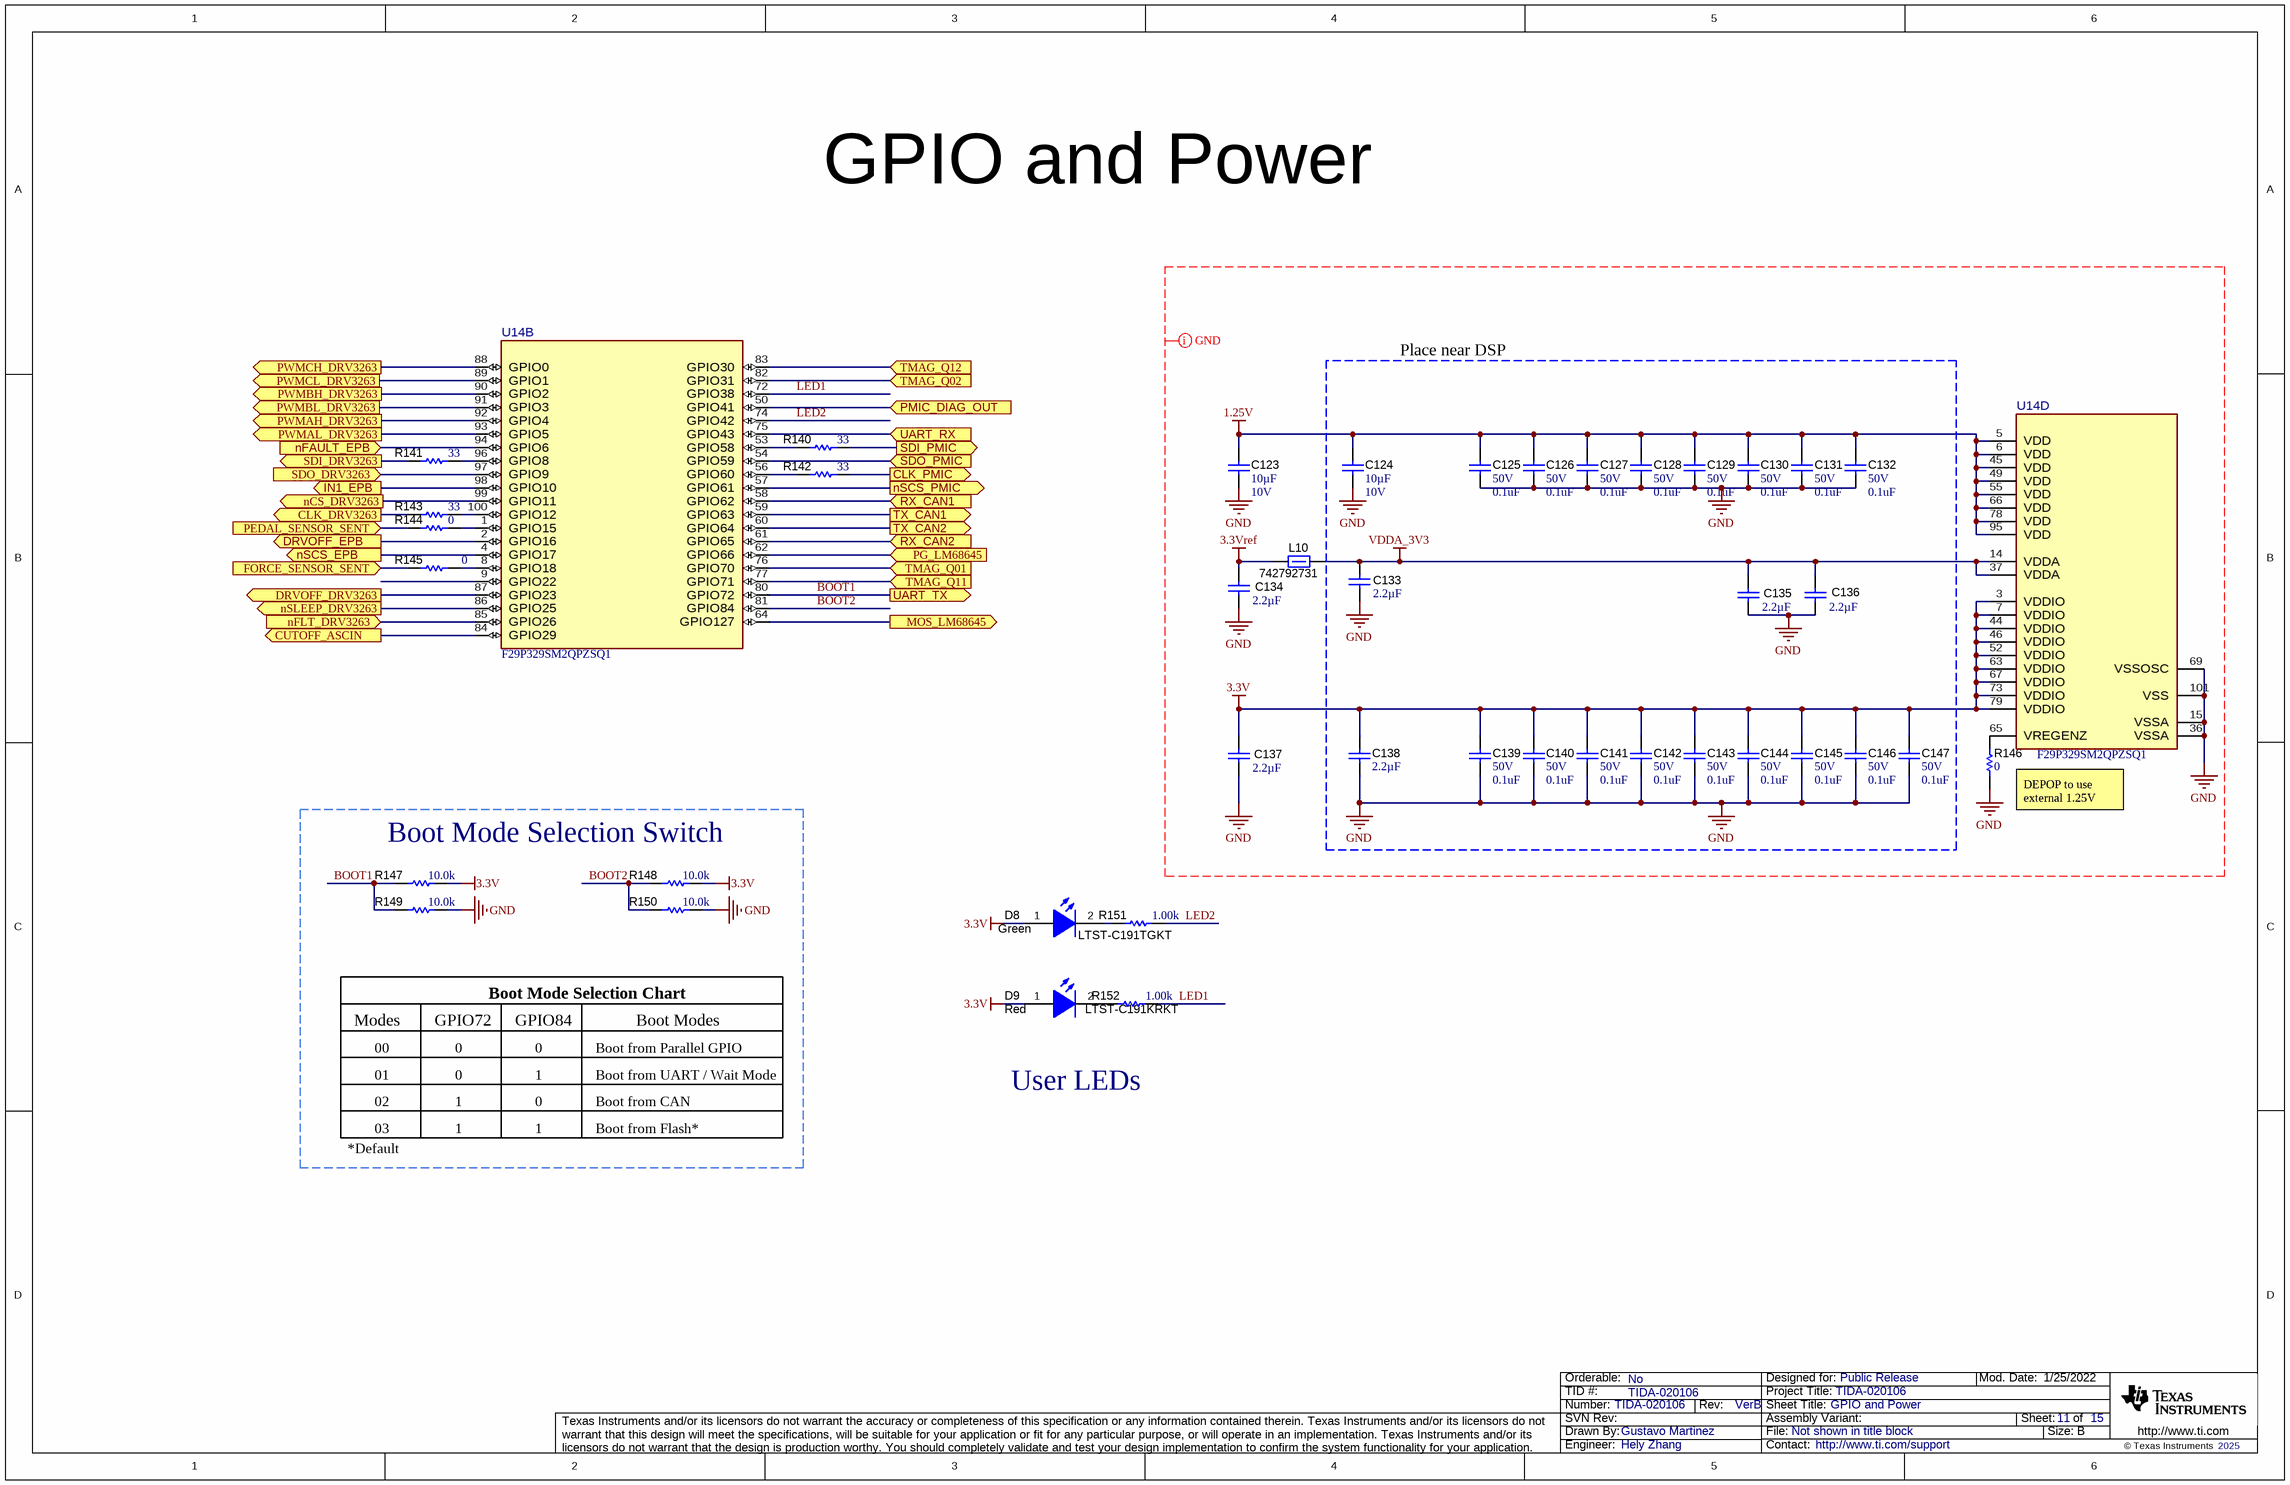
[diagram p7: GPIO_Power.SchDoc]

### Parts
C123  Cap_F: 10µF  VDC_V: 10V  [0603]  (hidden comment: GRM188Z71A106MA73D)
C124  Cap_F: 10µF  VDC_V: 10V  [0603]  (hidden comment: GRM188Z71A106MA73D)
C125  VDC_V: 50V  ValueDisplayed: 0.1uF  [0402]  (hidden comment: GCM155R71H104KE02D)
C126  VDC_V: 50V  ValueDisplayed: 0.1uF  [0402]  (hidden comment: GCM155R71H104KE02D)
C127  VDC_V: 50V  ValueDisplayed: 0.1uF  [0402]  (hidden comment: GCM155R71H104KE02D)
C128  VDC_V: 50V  ValueDisplayed: 0.1uF  [0402]  (hidden comment: GCM155R71H104KE02D)
C129  VDC_V: 50V  ValueDisplayed: 0.1uF  [0402]  (hidden comment: GCM155R71H104KE02D)
C130  VDC_V: 50V  ValueDisplayed: 0.1uF  [0402]  (hidden comment: GCM155R71H104KE02D)
C131  VDC_V: 50V  ValueDisplayed: 0.1uF  [0402]  (hidden comment: GCM155R71H104KE02D)
C132  VDC_V: 50V  ValueDisplayed: 0.1uF  [0402]  (hidden comment: GCM155R71H104KE02D)
C133  ValueDisplayed: 2.2µF  [0402]  (hidden comment: GRM155R61E225ME15D)
C134  ValueDisplayed: 2.2µF  [0402]  (hidden comment: GRM155R61E225ME15D)
C135  ValueDisplayed: 2.2µF  [0402]  (hidden comment: GRM155R61E225ME15D)
C136  ValueDisplayed: 2.2µF  [0402]  (hidden comment: GRM155R61E225ME15D)
C137  ValueDisplayed: 2.2µF  [0402]  (hidden comment: GRM155R61E225ME15D)
C138  ValueDisplayed: 2.2µF  [0402]  (hidden comment: GRM155R61E225ME15D)
C139  VDC_V: 50V  ValueDisplayed: 0.1uF  [0402]  (hidden comment: GCM155R71H104KE02D)
C140  VDC_V: 50V  ValueDisplayed: 0.1uF  [0402]  (hidden comment: GCM155R71H104KE02D)
C141  VDC_V: 50V  ValueDisplayed: 0.1uF  [0402]  (hidden comment: GCM155R71H104KE02D)
C142  VDC_V: 50V  ValueDisplayed: 0.1uF  [0402]  (hidden comment: GCM155R71H104KE02D)
C143  VDC_V: 50V  ValueDisplayed: 0.1uF  [0402]  (hidden comment: GCM155R71H104KE02D)
C144  VDC_V: 50V  ValueDisplayed: 0.1uF  [0402]  (hidden comment: GCM155R71H104KE02D)
C145  VDC_V: 50V  ValueDisplayed: 0.1uF  [0402]  (hidden comment: GCM155R71H104KE02D)
C146  VDC_V: 50V  ValueDisplayed: 0.1uF  [0402]  (hidden comment: GCM155R71H104KE02D)
C147  VDC_V: 50V  ValueDisplayed: 0.1uF  [0402]  (hidden comment: GCM155R71H104KE02D)
D8  LTST-C191TGKT  value Green  [LTST-C191_Green]
D9  LTST-C191KRKT  value Red  [LTST-C191_Red]
L10  742792731  [0402]
R140  ValueDisplayed: 33  [0402]  (hidden comment: CRCW040233R0JNED)
R141  ValueDisplayed: 33  [0402]  (hidden comment: CRCW040233R0JNED)
R142  ValueDisplayed: 33  [0402]  (hidden comment: CRCW040233R0JNED)
R143  ValueDisplayed: 33  [0402]  (hidden comment: CRCW040233R0JNED)
R144  ValueDisplayed: 0  [0402]  (hidden comment: CRCW04020000Z0ED)
R145  ValueDisplayed: 0  [0402]  (hidden comment: CRCW04020000Z0ED)
R146  ValueDisplayed: 0  [0402]  (hidden comment: CRCW04020000Z0ED)
R147  ValueDisplayed: 10.0k  [0402]  (hidden comment: CRCW040210K0FKED)
R148  ValueDisplayed: 10.0k  [0402]  (hidden comment: CRCW040210K0FKED)
R149  ValueDisplayed: 10.0k  [0402]  (hidden comment: CRCW040210K0FKED)
R150  ValueDisplayed: 10.0k  [0402]  (hidden comment: CRCW040210K0FKED)
R151  ValueDisplayed: 1.00k  [0402]  (hidden comment: CRCW04021K00FKED)
R152  ValueDisplayed: 1.00k  [0402]  (hidden comment: CRCW04021K00FKED)
U14  F29P329SM2QPZSQ1  [PZS0100A-MFG]  (parts B,D of 4)

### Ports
CLK_DRV3263 (out), CLK_PMIC (out), CUTOFF_ASCIN (out), DRVOFF_DRV3263 (out), DRVOFF_EPB (out), FORCE_SENSOR_SENT (in), IN1_EPB (out), MOS_LM68645 (out), nCS_DRV3263 (out), nFAULT_EPB (in), nFLT_DRV3263 (in), nSCS_EPB (out), nSCS_PMIC (out), nSLEEP_DRV3263 (out), PEDAL_SENSOR_SENT (in), PG_LM68645 (in), PMIC_DIAG_OUT (in), PWMAH_DRV3263 (out), PWMAL_DRV3263 (out), PWMBH_DRV3263 (out), PWMBL_DRV3263 (out), PWMCH_DRV3263 (out), PWMCL_DRV3263 (out), RX_CAN1 (in), RX_CAN2 (in), SDI_DRV3263 (out), SDI_PMIC (out), SDO_DRV3263 (in), SDO_PMIC (in), TMAG_Q01 (in), TMAG_Q02 (in), TMAG_Q11 (in), TMAG_Q12 (in), TX_CAN1 (out), TX_CAN2 (out), UART_RX (in), UART_TX (out)

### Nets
1.25V: C123.1 C124.1 C125.1 C126.1 C127.1 C128.1 C129.1 C130.1 C131.1 C132.1 U14.5(VDD) U14.6(VDD) U14.45(VDD) U14.49(VDD) U14.55(VDD) U14.66(VDD) U14.78(VDD) U14.95(VDD)
3.3V: C137.1 C138.2 C139.1 C140.1 C141.1 C142.1 C143.1 C144.1 C145.1 C146.1 C147.1 D8.1(A) D9.1(A) R147.1 R148.1 U14.3(VDDIO) U14.7(VDDIO) U14.44(VDDIO) U14.46(VDDIO) U14.52(VDDIO) U14.63(VDDIO) U14.67(VDDIO) U14.73(VDDIO) U14.79(VDDIO)
3.3Vref: C134.1 L10.2
GND: C123.2 C124.2 C125.2 C126.2 C127.2 C128.2 C129.2 C130.2 C131.2 C132.2 C133.2 C134.2 C135.2 C136.2 C137.2 C138.1 C139.2 C140.2 C141.2 C142.2 C143.2 C144.2 C145.2 C146.2 C147.2 R146.2 R149.1 R150.1 U14.15(VSSA) U14.36(VSSA) U14.69(VSSOSC) U14.101(VSS)
VDDA_3V3: C133.1 C135.1 C136.1 L10.1 U14.14(VDDA) U14.37(VDDA)
BOOT1: R147.2 R149.2 U14.80(GPIO72) ; port UART_TX
BOOT2: R148.2 R150.2 U14.81(GPIO84)
CLK_DRV3263: R143.1 ; port CLK_DRV3263
CLK_PMIC: R142.2 ; port CLK_PMIC
CUTOFF_ASCIN: U14.84(GPIO29) ; port CUTOFF_ASCIN
DRVOFF_DRV3263: U14.87(GPIO23) ; port DRVOFF_DRV3263
DRVOFF_EPB: U14.2(GPIO16) ; port DRVOFF_EPB
FORCE_SENSOR_SENT: R145.2 ; port FORCE_SENSOR_SENT
IN1_EPB: U14.98(GPIO10) ; port IN1_EPB
LED1: R152.2 U14.72(GPIO38)
LED2: R151.2 U14.74(GPIO42)
MOS_LM68645: U14.64(GPIO127) ; port MOS_LM68645
nCS_DRV3263: U14.99(GPIO11) ; port nCS_DRV3263
nFAULT_EPB: U14.94(GPIO6) ; port nFAULT_EPB
nFLT_DRV3263: U14.85(GPIO26) ; port nFLT_DRV3263
nSCS_EPB: U14.4(GPIO17) ; port nSCS_EPB
nSCS_PMIC: U14.57(GPIO61) ; port nSCS_PMIC
nSLEEP_DRV3263: U14.86(GPIO25) ; port nSLEEP_DRV3263
PEDAL_SENSOR_SENT: R144.2 ; port PEDAL_SENSOR_SENT
PG_LM68645: U14.62(GPIO66) ; port PG_LM68645
PMIC_DIAG_OUT: U14.50(GPIO41) ; port PMIC_DIAG_OUT
PWMAH: U14.92(GPIO4) ; port PWMAH_DRV3263
PWMAL: U14.93(GPIO5) ; port PWMAL_DRV3263
PWMBH: U14.90(GPIO2) ; port PWMBH_DRV3263
PWMBL: U14.91(GPIO3) ; port PWMBL_DRV3263
PWMCH: U14.88(GPIO0) ; port PWMCH_DRV3263
PWMCL: U14.89(GPIO1) ; port PWMCL_DRV3263
RX_CAN1: U14.58(GPIO62) ; port RX_CAN1
RX_CAN2: U14.61(GPIO65) ; port RX_CAN2
SDI_DRV3263: R141.1 ; port SDI_DRV3263
SDI_PMIC: R140.2 ; port SDI_PMIC
SDO_DRV3263: U14.97(GPIO9) ; port SDO_DRV3263
SDO_PMIC: U14.54(GPIO59) ; port SDO_PMIC
TMAG_Q01: U14.76(GPIO70) ; port TMAG_Q01
TMAG_Q02: U14.82(GPIO31) ; port TMAG_Q02
TMAG_Q11: U14.77(GPIO71) ; port TMAG_Q11
TMAG_Q12: U14.83(GPIO30) ; port TMAG_Q12
TX_CAN1: U14.59(GPIO63) ; port TX_CAN1
TX_CAN2: U14.60(GPIO64) ; port TX_CAN2
UART_RX: U14.75(GPIO43) ; port UART_RX
NetD8_2: D8.2(K) R151.1
NetD9_2: D9.2(K) R152.1
NetR140_1: R140.1 U14.53(GPIO58)
NetR141_2: R141.2 U14.96(GPIO8)
NetR142_1: R142.1 U14.56(GPIO60)
NetR143_2: R143.2 U14.100(GPIO12)
NetR144_1: R144.1 U14.1(GPIO15)
NetR145_1: R145.1 U14.8(GPIO18)
NetR146_1: R146.1 U14.65(VREGENZ)

Not connected (* = marked no-connect by the designer): U14 9(GPIO22)

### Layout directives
net class GND: 1.25V, 3.3V, 3.3Vref, GND, VDDA_3V3

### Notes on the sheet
- GPIO and Power
- Place near DSP
- DEPOP to use external 1.25V
- Boot Mode Selection Switch
- Modes
- GPIO72
- Boot Mode Selection Chart
- GPIO84
- Boot Modes
- 00
- 01
- 02
- 0
- 1
- Boot from Parallel GPIO
- Boot from UART / Wait Mode
- Boot from CAN
- User LEDs
- *Default
- 03
- Boot from Flash*

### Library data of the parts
C123 C124 = CMP-0007497-1: CAP, CERM, 10 uF, 10 V, +/- 20%, X7R, 0603; Manufacturer: MuRata; TaMin_C: -55°C; Polarized: N; SizeAreaWB_mm2: 4.68; Value1: Unknown; U/M: EA; Value: 10uF; TaMax_C: 125°C; SizeZ_mm: 1; SizeX_mm: 1.6; SizeY_mm: 0.8; SizeArea_mm2: 1.28; AEC Category: Q200
C125-C132 C139-C147 = CMP-0006356-2: as C3 on sheet Main
C133-C138 = CMP-0081010-1: CAP, CERM, 2.2 µF, 25 V,+/- 20%, X5R, 0402; Manufacturer: MuRata; TaMin_C: -55°C; Polarized: N; SizeAreaWB_mm2: 3; U/M: EA; Value: 2.2uF; TaMax_C: 85°C; SizeZ_mm: 0.6; SizeX_mm: 1; SizeY_mm: 0.5; Value2: 25V; AEC Category: Q200
D8 = CMP-0002891-1: LED, Green, SMD; Manufacturer: Lite-On; Io_A: 20mA; Value1: W; U/M: EA; Vf_V: 3.2V; Type: InGaN
D9 = CMP-0002950-1: LED, Red, SMD; Manufacturer: Lite-On; Io_A: 20mA; Power_TotalModule: 75mW; Vr_V: 5V; Tjmax_C: 85°C; Value1: 0.075W; U/M: EA; Angle: 130; Ir_A: 10µA; Vf_V: 2V; Type: AlInGaP
L10 = CMP-0003235-1: as L7 on sheet ADC
R140-R143 = CMP-0026908-3: as R133 on sheet Clock_Reset
R144-R146 = CMP-0026822-3: as R22 on sheet DC_DC
R147-R150 = CMP-0025958-3: as R5 on sheet Main
R151 R152 = CMP-0026071-3: as R24 on sheet DC_DC
U14 = CMP-0128482-1: as U14 on sheet Clock_Reset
